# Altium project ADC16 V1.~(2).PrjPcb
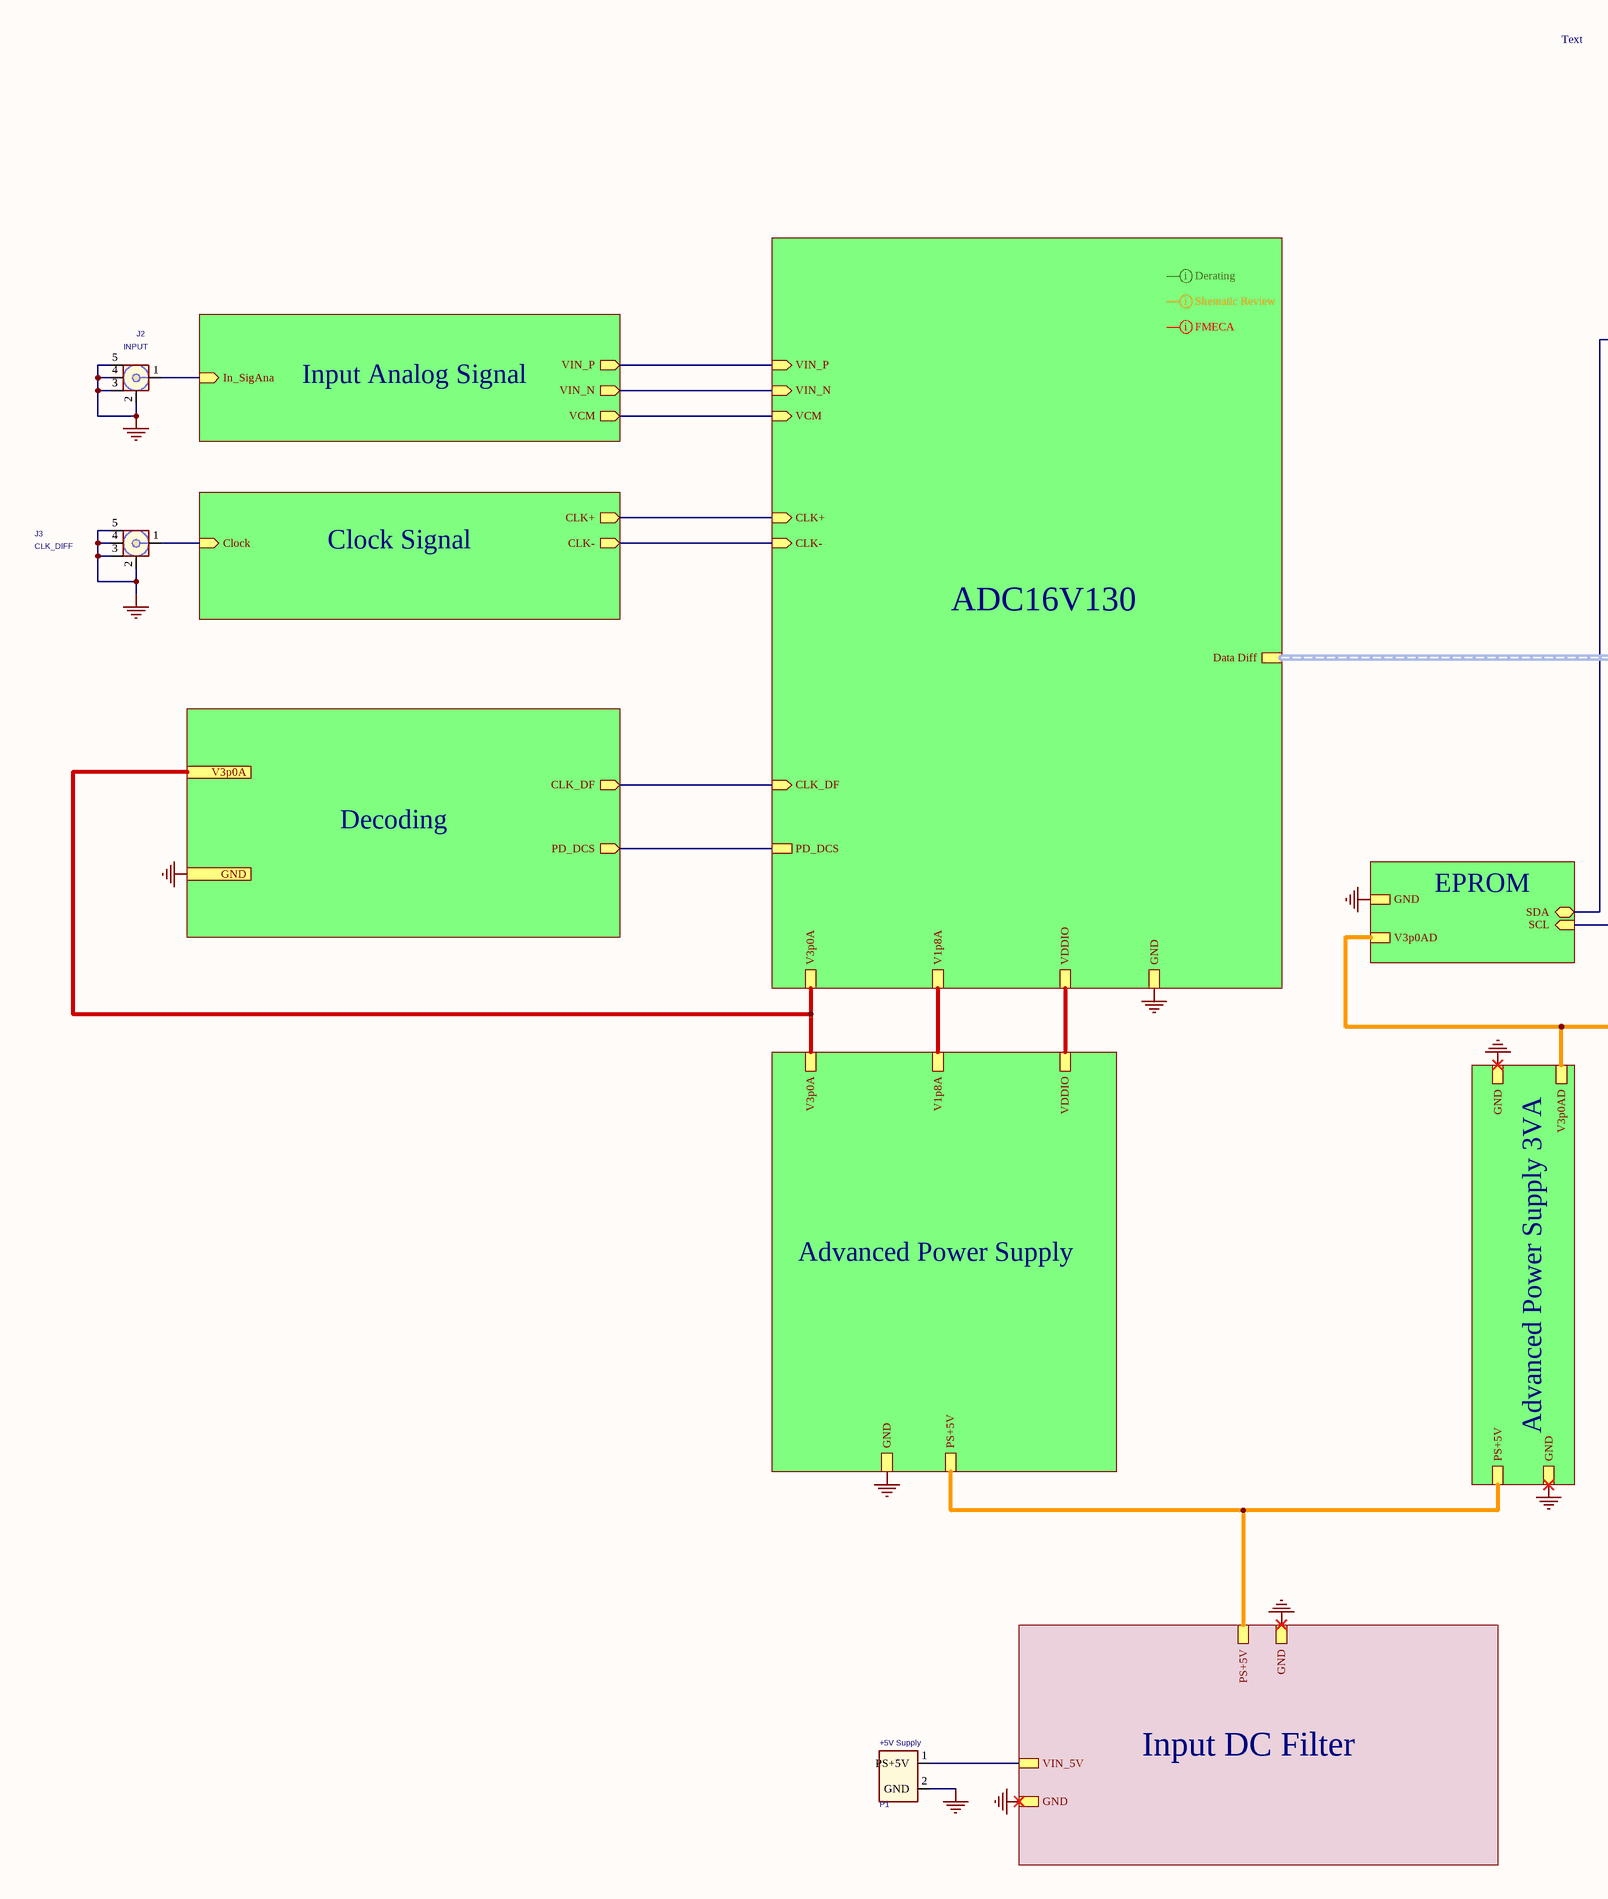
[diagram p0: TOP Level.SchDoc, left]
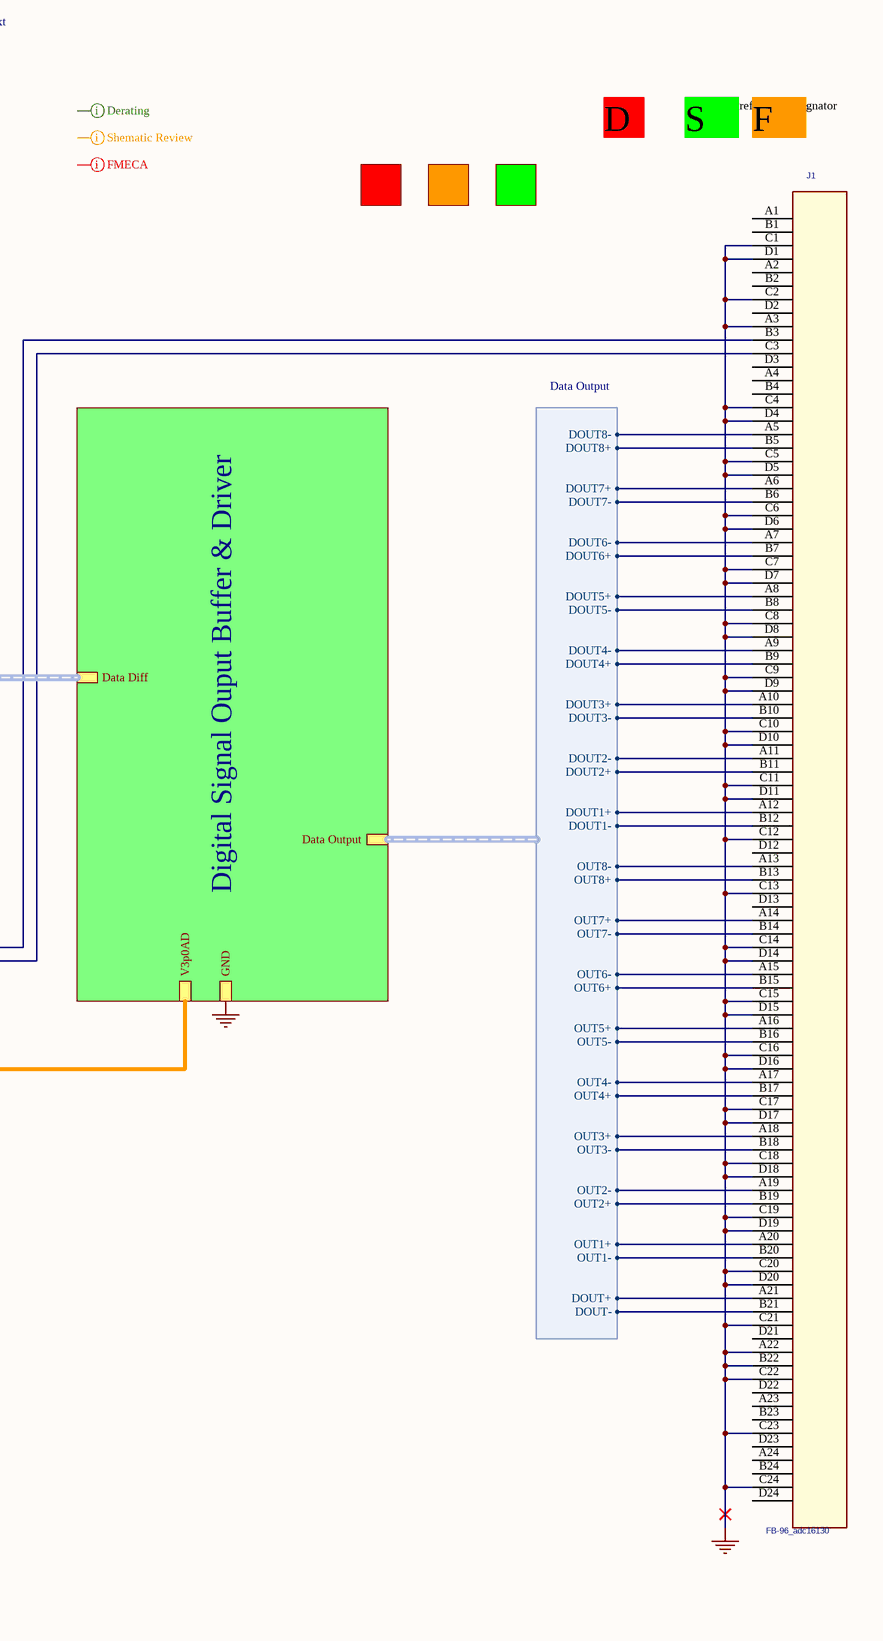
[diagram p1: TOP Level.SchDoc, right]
Revision: 1
13 sheets, 121 parts. Net scope: hierarchical (ports join the sheet entries above them; power ports are global).
Sheets:
  TOP Level.SchDoc
    ADC16V130 = [4]ADC16V130.SchDoc
    Digital Signal Ouput Buffer & Driver = [5]Digital Signal Ouput Buffer & Driver.SchDoc
    Clock Signal = [6]Clock Signal.SchDoc
    EPROM = [8]Eeprom.SchDoc
    Input Analog Signal = [9]Input Analog Signal.SchDoc
    Advanced Power Supply 3VA = [11]Advanced Power Supply 3VA.SchDoc
    Input DC Filter = [12]Input DC Filter.SchDoc
    Decoding = Decoding.SchDoc
      Decoding Code1 = [1]Decoding Code1.SchDoc
      Decoding Code2 = [10]Decoding Code2.SchDoc
    Advanced Power Supply = Advanced Power Supply.SchDoc
      Advanced Power Supply ADC1.8V = [7]Advanced Power Supply for ADC1.8V.SchDoc

## Sheet TOP Level.SchDoc: BQR Evaluation Project based on TI
size A2; Organization: BQR; Address1: Reliability Engineering; Address2: Optimized Maintenance; Address3: www.bqr.com; Address4: www.bqr-digital.com; DocumentNumber: DOC1; SheetNumber: 1; SheetTotal: 13

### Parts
J1  FB-96_adc16130  [con96-fb_16130]
J2  INPUT  [RFSMAVCLRJ8]
J3  CLK_DIFF  [RFSMAVCLRJ8]
P1  +5V Supply  [tb-2pos_plug]

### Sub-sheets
ADC16V130 = [4]ADC16V130.SchDoc: VCM (in), VIN_P (in), VIN_N (in), CLK+ (in), CLK- (in), V3p0A, PD_DCS, V1p8A, VDDIO, GND, CLK_DF (in), Data Diff (harness Data Diff)
Advanced Power Supply = Advanced Power Supply.SchDoc: PS+5V, V3p0A, GND, V1p8A, VDDIO
Advanced Power Supply 3VA = [11]Advanced Power Supply 3VA.SchDoc: V3p0AD, PS+5V, GND, GND
Clock Signal = [6]Clock Signal.SchDoc: CLK+ (out), CLK- (out), Clock (in)
Decoding = Decoding: CLK_DF (out), PD_DCS (out)
Digital Signal Ouput Buffer & Driver = [5]Digital Signal Ouput Buffer & Driver.SchDoc: V3p0AD, GND, Data Diff (harness Data Diff), Data Output (harness Data Output)
EPROM = [8]Eeprom.SchDoc: SDA (bidir), SCL (in), V3p0AD, GND
Input Analog Signal = [9]Input Analog Signal.SchDoc: VIN_P (out), VIN_N (out), VCM (out), In_SigAna (in)
Input DC Filter = [12]Input DC Filter.SchDoc: PS+5V, VIN_5V, GND, GND

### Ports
GND, V3p0A

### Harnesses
Data Output: DOUT1+, DOUT1-, DOUT2+, DOUT2-, DOUT3+, DOUT3-, DOUT4+, DOUT4-, DOUT5+, DOUT5-, DOUT6+, DOUT6-, DOUT7+, DOUT7-, DOUT8+, DOUT8-, DOUT+, DOUT-, OUT1+, OUT1-, OUT2+, OUT2-, OUT3+, OUT3-, OUT4+, OUT4-, OUT5+, OUT5-, OUT6+, OUT6-, OUT7+, OUT7-, OUT8+, OUT8-

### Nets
GND: J1.A3 J1.A22 J1.B22 J1.C1 J1.C2 J1.C4 J1.C5 J1.C6 J1.C7 J1.C8 J1.C9 J1.C10 J1.C11 J1.C12 J1.C13 J1.C14 J1.C15 J1.C16 J1.C17 J1.C18 J1.C19 J1.C20 J1.C21 J1.C22 J1.C23 J1.C24 J1.D1 J1.D4 J1.D5 J1.D6 J1.D7 J1.D8 J1.D9 J1.D10 J1.D11 J1.D14 J1.D15 J1.D16 J1.D17 J1.D18 J1.D19 J1.D20 J2.2(SHIELD2) J2.3(SHIELD3) J2.4(SHIELD4) J2.5(SHIELD5) J3.2(SHIELD2) J3.3(SHIELD3) J3.4(SHIELD4) J3.5(SHIELD5) P1.2(GND) ; port GND, sheet ADC16V130/GND, sheet Digital Signal Ouput Buffer & Driver/GND, sheet EPROM/GND, sheet Advanced Power Supply 3VA/PS+5V, sheet Advanced Power Supply 3VA/GND, sheet Advanced Power Supply 3VA/GND, sheet Input DC Filter/PS+5V, sheet Input DC Filter/GND, sheet Input DC Filter/GND, sheet Advanced Power Supply/PS+5V, sheet Advanced Power Supply/GND
V1p8A: sheet ADC16V130/V1p8A, sheet Advanced Power Supply/V1p8A
V3p0A: port V3p0A, sheet ADC16V130/V3p0A, sheet Advanced Power Supply/V3p0A
V3p0AD: sheet Digital Signal Ouput Buffer & Driver/V3p0AD, sheet EPROM/V3p0AD, sheet Advanced Power Supply 3VA/V3p0AD
VDDIO: sheet ADC16V130/VDDIO, sheet Advanced Power Supply/VDDIO
DOUT1+: J1.A12 ; sheet Digital Signal Ouput Buffer & Driver/Data Output.DOUT1+
DOUT1-: J1.B12 ; sheet Digital Signal Ouput Buffer & Driver/Data Output.DOUT1-
DOUT2+: J1.B11 ; sheet Digital Signal Ouput Buffer & Driver/Data Output.DOUT2+
DOUT2-: J1.A11 ; sheet Digital Signal Ouput Buffer & Driver/Data Output.DOUT2-
DOUT3+: J1.A10 ; sheet Digital Signal Ouput Buffer & Driver/Data Output.DOUT3+
DOUT3-: J1.B10 ; sheet Digital Signal Ouput Buffer & Driver/Data Output.DOUT3-
DOUT4+: J1.B9 ; sheet Digital Signal Ouput Buffer & Driver/Data Output.DOUT4+
DOUT4-: J1.A9 ; sheet Digital Signal Ouput Buffer & Driver/Data Output.DOUT4-
DOUT5+: J1.A8 ; sheet Digital Signal Ouput Buffer & Driver/Data Output.DOUT5+
DOUT5-: J1.B8 ; sheet Digital Signal Ouput Buffer & Driver/Data Output.DOUT5-
DOUT6+: J1.B7 ; sheet Digital Signal Ouput Buffer & Driver/Data Output.DOUT6+
DOUT6-: J1.A7 ; sheet Digital Signal Ouput Buffer & Driver/Data Output.DOUT6-
DOUT7+: J1.A6 ; sheet Digital Signal Ouput Buffer & Driver/Data Output.DOUT7+
DOUT7-: J1.B6 ; sheet Digital Signal Ouput Buffer & Driver/Data Output.DOUT7-
DOUT8+: J1.B5 ; sheet Digital Signal Ouput Buffer & Driver/Data Output.DOUT8+
DOUT8-: J1.A5 ; sheet Digital Signal Ouput Buffer & Driver/Data Output.DOUT8-
DOUT+: J1.A21 ; sheet Digital Signal Ouput Buffer & Driver/Data Output.DOUT+
DOUT-: J1.B21 ; sheet Digital Signal Ouput Buffer & Driver/Data Output.DOUT-
OUT1+: J1.A20 ; sheet Digital Signal Ouput Buffer & Driver/Data Output.OUT1+
OUT1-: J1.B20 ; sheet Digital Signal Ouput Buffer & Driver/Data Output.OUT1-
OUT2+: J1.B19 ; sheet Digital Signal Ouput Buffer & Driver/Data Output.OUT2+
OUT2-: J1.A19 ; sheet Digital Signal Ouput Buffer & Driver/Data Output.OUT2-
OUT3+: J1.A18 ; sheet Digital Signal Ouput Buffer & Driver/Data Output.OUT3+
OUT3-: J1.B18 ; sheet Digital Signal Ouput Buffer & Driver/Data Output.OUT3-
OUT4+: J1.B17 ; sheet Digital Signal Ouput Buffer & Driver/Data Output.OUT4+
OUT4-: J1.A17 ; sheet Digital Signal Ouput Buffer & Driver/Data Output.OUT4-
OUT5+: J1.A16 ; sheet Digital Signal Ouput Buffer & Driver/Data Output.OUT5+
OUT5-: J1.B16 ; sheet Digital Signal Ouput Buffer & Driver/Data Output.OUT5-
OUT6+: J1.B15 ; sheet Digital Signal Ouput Buffer & Driver/Data Output.OUT6+
OUT6-: J1.A15 ; sheet Digital Signal Ouput Buffer & Driver/Data Output.OUT6-
OUT7+: J1.A14 ; sheet Digital Signal Ouput Buffer & Driver/Data Output.OUT7+
OUT7-: J1.B14 ; sheet Digital Signal Ouput Buffer & Driver/Data Output.OUT7-
OUT8+: J1.B13 ; sheet Digital Signal Ouput Buffer & Driver/Data Output.OUT8+
OUT8-: J1.A13 ; sheet Digital Signal Ouput Buffer & Driver/Data Output.OUT8-
VIN_5V: P1.1(PS+5V) ; sheet Input DC Filter/VIN_5V
NetC1_1: sheet ADC16V130/VCM, sheet Input Analog Signal/VCM
NetC17_1: J2.1(CENTER) ; sheet Input Analog Signal/In_SigAna
NetC21_1: sheet ADC16V130/VIN_P, sheet Input Analog Signal/VIN_P
NetC21_2: sheet ADC16V130/VIN_N, sheet Input Analog Signal/VIN_N
NetC32_1: J3.1(CENTER) ; sheet Clock Signal/Clock
NetC35_1: sheet ADC16V130/CLK+, sheet Clock Signal/CLK+
NetC35_2: sheet ADC16V130/CLK-, sheet Clock Signal/CLK-
NetJ1_B3: J1.B3 ; sheet EPROM/SDA
NetJ1_C3: J1.C3 ; sheet EPROM/SCL
NetJP1_2: sheet ADC16V130/CLK_DF, sheet Decoding/CLK_DF
NetJP2_2: sheet ADC16V130/PD_DCS, sheet Decoding/PD_DCS

Not connected (* = marked no-connect by the designer): J1 A1(1) A2(5) A4(13) A23(89) A24(93) B1(2) B2(6) B4(14) B23(90) B24(94) D2(8) D3(12) D12(48) D13(52) D21(84) D22(88) D23(92) D24(96)

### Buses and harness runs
harness sheet ADC16V130/Data Diff = sheet Digital Signal Ouput Buffer & Driver/Data Diff

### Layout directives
BQR1: Stam1: (no net found under the mark)
mark named Shematic Review: (no net found under the mark)
mark named FMECA: (no net found under the mark)
mark named Derating: (no net found under the mark)

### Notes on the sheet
- Text
- D
- Type @ to refer to a designator
- S
- F

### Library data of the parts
J1 = CON-FB96-ADC16130: 2MM FB,IS,ASY,024,SIG,HDR,SL; Manufacturer: AMP/Tyco; Manufacturer P/N: 223514-1; fiX_Manuf: JOHNSON; Catalog Number: CON00005; fiX_Func: Buffer & Driver (9)
J2 = SMA_CONN_4: SMA Connector Jack, Female Socket 50 Ohm Board Edge, End Launch Solder Tab; Manufacturer: JOHNSON; Manufacturer P/N: 142-0701-851; fiX_Manuf: Samtec; Catalog Number: CON00004; fiX_Func: Input circuit (4)
J3 = SMA_CONN_5: SMA Connector Jack, Female Socket 50 Ohm Board Edge, End Launch Solder Tab; Manufacturer P/N: 142-0701-851; Manufacturer: JOHNSON; fiX_Manuf: Samtec; Catalog Number: CON00004; fiX_Func: Clock signal (6)
P1 = TB2_1: CONN RCPT SUR 2POS .8MM TIN; Manufacturer P/N: 02SUR-32S; Manufacturer: JST; fiX_Manuf: Vishay; Catalog Number: CON00003; fiX_Func: DC Filter (12); SDTA_V(Vdiel): 5

## Sheet [4]ADC16V130.SchDoc: ADC16V130
size A3; Organization: BQR; Address1: Reliability Engineering; Address2: Optimized Maintenance; Address3: www.bqr.com; Address4: www.bqr-digital.com; DocumentNumber: DOC5; SheetNumber: 2; SheetTotal: 13
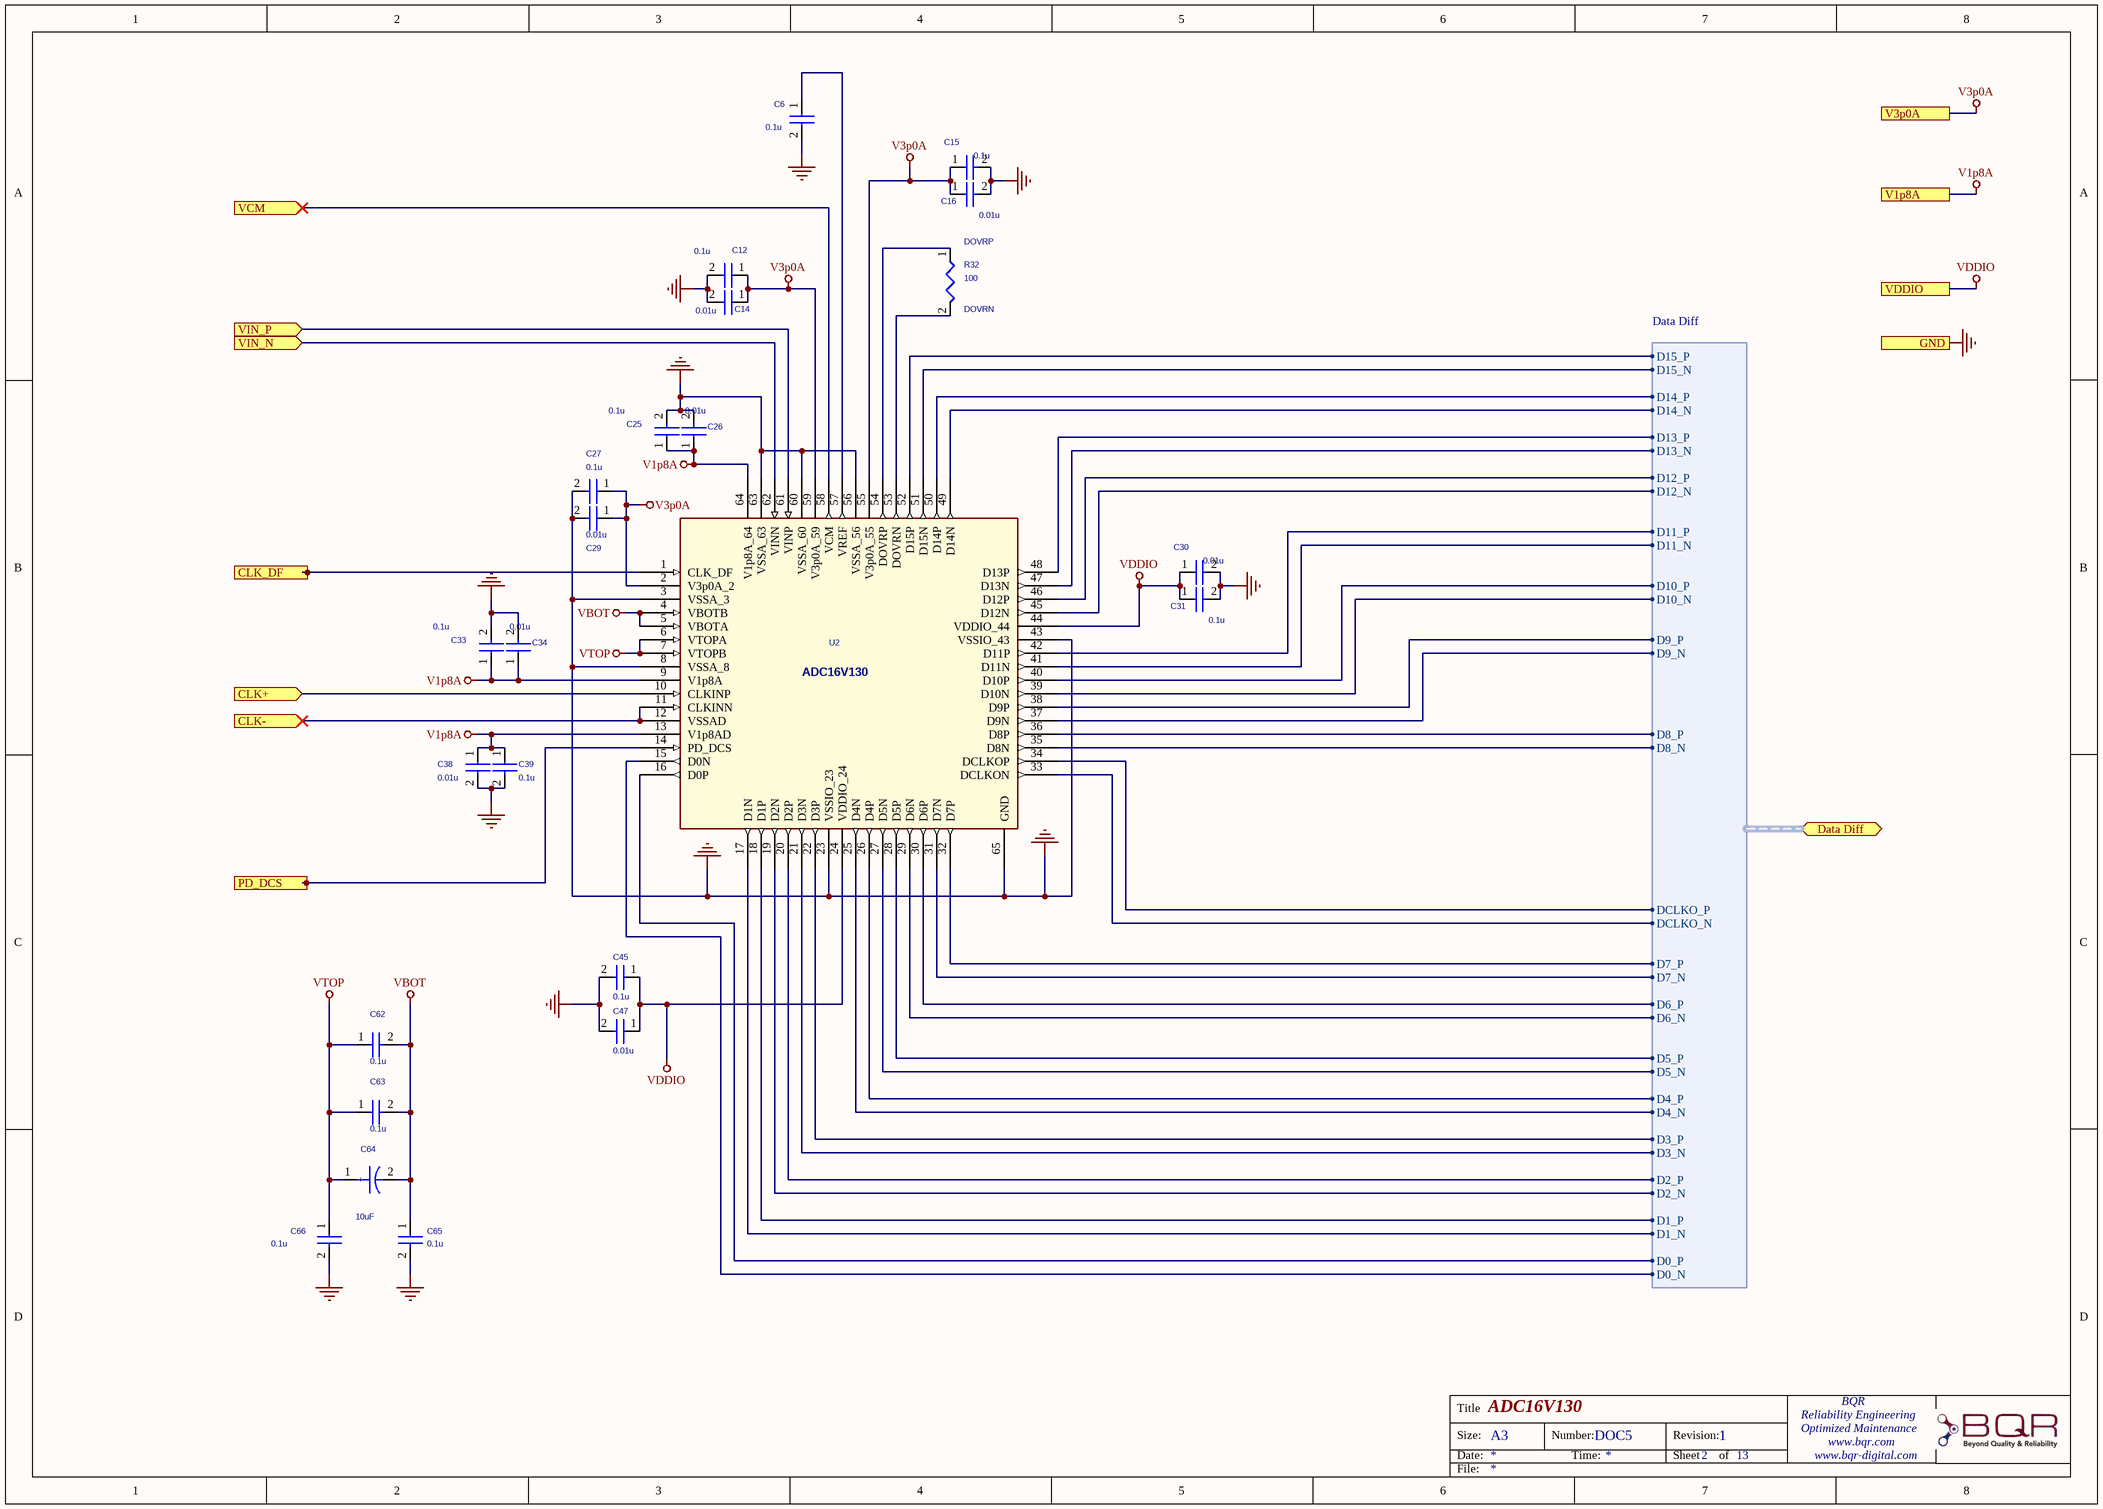
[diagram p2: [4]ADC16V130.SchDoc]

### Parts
C6  0.1u  [0402]
C12  0.1u  [0201]
C14  0.01u  [0402]
C15  0.1u  [0201]
C16  0.01u  [0402]
C25  0.1u  [0201]
C26  0.01u  [0402]
C27  0.1u  [0402]
C29  0.01u  [0402]
C30  0.01u  [0402]
C31  0.1u  [0402]
C33  0.1u  [0402]
C34  0.01u  [0402]
C38  0.01u  [0402]
C39  0.1u  [0402]
C45  0.1u  [0402]
C47  0.01u  [0402]
C62  0.1u  [0402]
C63  0.1u  [0402]
C64  10uF  [cap_a-case]
C65  0.1u  [0402]
C66  0.1u  [0402]
R32  100  [0402]
U2  ADC16V130  [llp64_16130_no-skt]

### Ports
CLK+ (in), CLK- (in), CLK_DF (in), Data Diff (bidir, harness Data Diff), GND, PD_DCS, V1p8A, V3p0A, VCM (in), VDDIO, VIN_N (in), VIN_P (in)

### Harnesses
Data Diff: D0_N, D0_P, D1_N, D1_P, D2_N, D2_P, D3_N, D3_P, D4_N, D4_P, D5_N, D5_P, D6_N, D6_P, D7_N, D7_P, D8_N, D8_P, D9_N, D9_P, D10_N, D10_P, D11_N, D11_P, D12_N, D12_P, D13_N, D13_P, D14_N, D14_P, D15_N, D15_P, DCLKO_N, DCLKO_P

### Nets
GND: C6.2 C12.2 C14.2 C15.2 C16.2 C25.2 C26.2 C27.2 C29.2 C30.2 C31.2 C33.2 C34.2 C38.2 C39.2 C45.2 C47.2 C65.2 C66.2 U2.3(VSSA_3) U2.8(VSSA_8) U2.23(VSSIO_23) U2.43(VSSIO_43) U2.56(VSSA_56) U2.60(VSSA_60) U2.63(VSSA_63) U2.65(GND) ; port GND
V1p8A: C25.1 C26.1 C33.1 C34.1 C38.1 C39.1 U2.9(V1p8A) U2.13(V1p8AD) U2.64(V1p8A_64) ; port V1p8A
V3p0A: C12.1 C14.1 C15.1 C16.1 C27.1 C29.1 U2.2(V3p0A_2) U2.55(V3p0A_55) U2.59(V3p0A_59) ; port V3p0A
VBOT: C62.2 C63.2 C64.2 C65.1 U2.4(VBOTB) U2.5(VBOTA)
VDDIO: C30.1 C31.1 C45.1 C47.1 U2.24(VDDIO_24) U2.44(VDDIO_44) ; port VDDIO
VTOP: C62.1 C63.1 C64.1 C66.1 U2.6(VTOPA) U2.7(VTOPB)
D0_N: U2.15(D0N) ; port Data Diff.D0_N
D0_P: U2.16(D0P) ; port Data Diff.D0_P
D1_N: U2.17(D1N) ; port Data Diff.D1_N
D1_P: U2.18(D1P) ; port Data Diff.D1_P
D2_N: U2.19(D2N) ; port Data Diff.D2_N
D2_P: U2.20(D2P) ; port Data Diff.D2_P
D3_N: U2.21(D3N) ; port Data Diff.D3_N
D3_P: U2.22(D3P) ; port Data Diff.D3_P
D4_N: U2.25(D4N) ; port Data Diff.D4_N
D4_P: U2.26(D4P) ; port Data Diff.D4_P
D5_N: U2.27(D5N) ; port Data Diff.D5_N
D5_P: U2.28(D5P) ; port Data Diff.D5_P
D6_N: U2.29(D6N) ; port Data Diff.D6_N
D6_P: U2.30(D6P) ; port Data Diff.D6_P
D7_N: U2.31(D7N) ; port Data Diff.D7_N
D7_P: U2.32(D7P) ; port Data Diff.D7_P
D8_N: U2.35(D8N) ; port Data Diff.D8_N
D8_P: U2.36(D8P) ; port Data Diff.D8_P
D9_N: U2.37(D9N) ; port Data Diff.D9_N
D9_P: U2.38(D9P) ; port Data Diff.D9_P
D10_N: U2.39(D10N) ; port Data Diff.D10_N
D10_P: U2.40(D10P) ; port Data Diff.D10_P
D11_N: U2.41(D11N) ; port Data Diff.D11_N
D11_P: U2.42(D11P) ; port Data Diff.D11_P
D12_N: U2.45(D12N) ; port Data Diff.D12_N
D12_P: U2.46(D12P) ; port Data Diff.D12_P
D13_N: U2.47(D13N) ; port Data Diff.D13_N
D13_P: U2.48(D13P) ; port Data Diff.D13_P
D14_N: U2.49(D14N) ; port Data Diff.D14_N
D14_P: U2.50(D14P) ; port Data Diff.D14_P
D15_N: U2.51(D15N) ; port Data Diff.D15_N
D15_P: U2.52(D15P) ; port Data Diff.D15_P
DCLKO_N: U2.33(DCLKON) ; port Data Diff.DCLKO_N
DCLKO_P: U2.34(DCLKOP) ; port Data Diff.DCLKO_P
NetC1_1: U2.58(VCM) ; port VCM
NetC6_1: C6.1 U2.57(VREF)
NetC21_1: U2.61(VINP) ; port VIN_P
NetC21_2: U2.62(VINN) ; port VIN_N
NetC35_1: U2.10(CLKINP) ; port CLK+
NetC35_2: U2.11(CLKINN) U2.12(VSSAD) ; port CLK-
NetJP1_2: U2.1(CLK_DF) ; port CLK_DF
NetJP2_2: U2.14(PD_DCS) ; port PD_DCS
NetR32_1: R32.1 U2.54(DOVRP)
NetR32_2: R32.2 U2.53(DOVRN)

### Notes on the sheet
- (near R32) DOVRP
- (near R32) DOVRN

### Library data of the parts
C6 = Capacitor_4: CAP CER 0.1UF 10V X5R 0402; Manufacturer P/N: GRM155R61A104KA01D; Manufacturer: Murata; Catalog Number: CAP00026; fiX_Func: ADC (10)
C12 C15 = Cap_1: CAP CER 0.1UF 6.3V X5R 0201; Manufacturer P/N: GRM033R60J104KE19D; Manufacturer: Murata; Catalog Number: CAP00002; SDTA_V(Voltage): 3; fiX_Func: ADC (10); SDTA_V(): 5
C14 C16 C29 = Cap_1: CAP CER 10000PF 50V X7R 0402; Manufacturer P/N: GRM155R71H103KA88D; Manufacturer: Murata; Catalog Number: CAP00027; SDTA_V(Voltage): 3; fiX_Func: ADC (10); SDTA_V(): 5
C25 = Cap_1: CAP CER 0.1UF 6.3V X5R 0201; Manufacturer P/N: GRM033R60J104KE19D; Manufacturer: Murata; Catalog Number: CAP00002; SDTA_V(Voltage): 1.8; fiX_Func: ADC (10)
C26 C34 = Cap_1: CAP CER 10000PF 50V X7R 0402; Manufacturer P/N: GRM155R71H103KA88D; Manufacturer: Murata; Catalog Number: CAP00027; SDTA_V(Voltage): 1.8; fiX_Func: ADC (10)
C27 = Cap_1: CAP CER 0.1UF 10V X5R 0402; Manufacturer P/N: GRM155R61A104KA01D; Manufacturer: Murata; Catalog Number: CAP00026; SDTA_V(Voltage): 3; fiX_Func: ADC (10); SDTA_V(): 5
C30 = Cap_1: CAP CER 10000PF 50V X7R 0402; Manufacturer P/N: GRM155R71H103KA88D; Manufacturer: Murata; Catalog Number: CAP00027; SDTA_V(Voltage): 25; fiX_Func: Buffer & Driver (9)
C31 = Cap_1: CAP CER 0.1UF 10V X5R 0402; Manufacturer P/N: GRM155R61A104KA01D; Manufacturer: Murata; Catalog Number: CAP00026; SDTA_V(Voltage): 25; fiX_Func: Buffer & Driver (9)
C33 C39 = Cap_1: CAP CER 0.1UF 10V X5R 0402; Manufacturer P/N: GRM155R61A104KA01D; Manufacturer: Murata; Catalog Number: CAP00026; SDTA_V(Voltage): 1.8; fiX_Func: ADC (10)
C38 = Cap_1: CAP CER 10000PF 50V X7R 0402; Manufacturer P/N: GRM155R71H103KA88D; Manufacturer: Murata; Catalog Number: CAP00027; SDTA_V(Voltage): 1.8; fiX_Func: Advanced Power Supply 1.8V (3)
C45 = Cap_1: CAP CER 0.1UF 10V X5R 0402; Manufacturer P/N: GRM155R61A104KA01D; Manufacturer: Murata; Catalog Number: CAP00026; SDTA_V(Voltage): 25; fiX_Func: ADC (10)
C47 = Cap_1: CAP CER 10000PF 50V X7R 0402; Manufacturer P/N: GRM155R71H103KA88D; Manufacturer: Murata; Catalog Number: CAP00027; SDTA_V(Voltage): 25; fiX_Func: ADC (10)
C62 C63 = Capacitor_3: CAP CER 0.1UF 10V X5R 0402; Manufacturer P/N: GRM155R61A104KA01D; Manufacturer: Murata; Catalog Number: CAP00026; fiX_Func: ADC (10)
C64 = Cap_Polar_1: CAP TANT 10UF 10V 20% 1206; Manufacturer P/N: F931A106MAA; Manufacturer: Nichicon; fiX_Manuf: Murata; Catalog Number: CAP00023; fiX_Func: ADC (10)
C65 = Capacitor_4: CAP CER 0.1UF 10V X5R 0402; Manufacturer P/N: GRM155R61A104KA01D; Manufacturer: Murata; Catalog Number: CAP00026; fiX_Func: ADC (10); SDTA_V(Voltage): 35
C66 = Capacitor_4: CAP CER 0.1UF 10V X5R 0402; Manufacturer P/N: GRM155R61A104KA01D; Manufacturer: Murata; Catalog Number: CAP00026; fiX_Func: ADC (10); SDTA_V(Voltage): 21
R32 = Resistor_3: RES SMD 100 OHM 1% 1/16W 0402; Manufacturer: Vishay; Manufacturer P/N: CRCW0402100RFKED; Catalog Number: RES00014; fiX_Func: ADC (10)
U2 = ADC16130_LLP_13: IC ADC 16BIT 130MSPS LVDS 64WQFN; Manufacturer P/N: ADC16V130CISQE/NOPB; Manufacturer: Texas Instruments; fiX_Manuf: Atmel; Catalog Number: IC00007; SDTA_I(Iout): 0.01; SDTA_P(Power): 0.2; SDTA_Par6(Freq[Mhz]): 10; SDTA_V(Vsupply): 5; fiX_Func: ADC (10)

## Sheet [5]Digital Signal Ouput Buffer & Driver.SchDoc: Digital Signal Ouput Buffer & Driver
size A2; Organization: BQR; Address1: Reliability Engineering; Address2: Optimized Maintenance; Address3: www.bqr.com; Address4: www.bqr-digital.com; DocumentNumber: DOC6; SheetNumber: 3; SheetTotal: 13
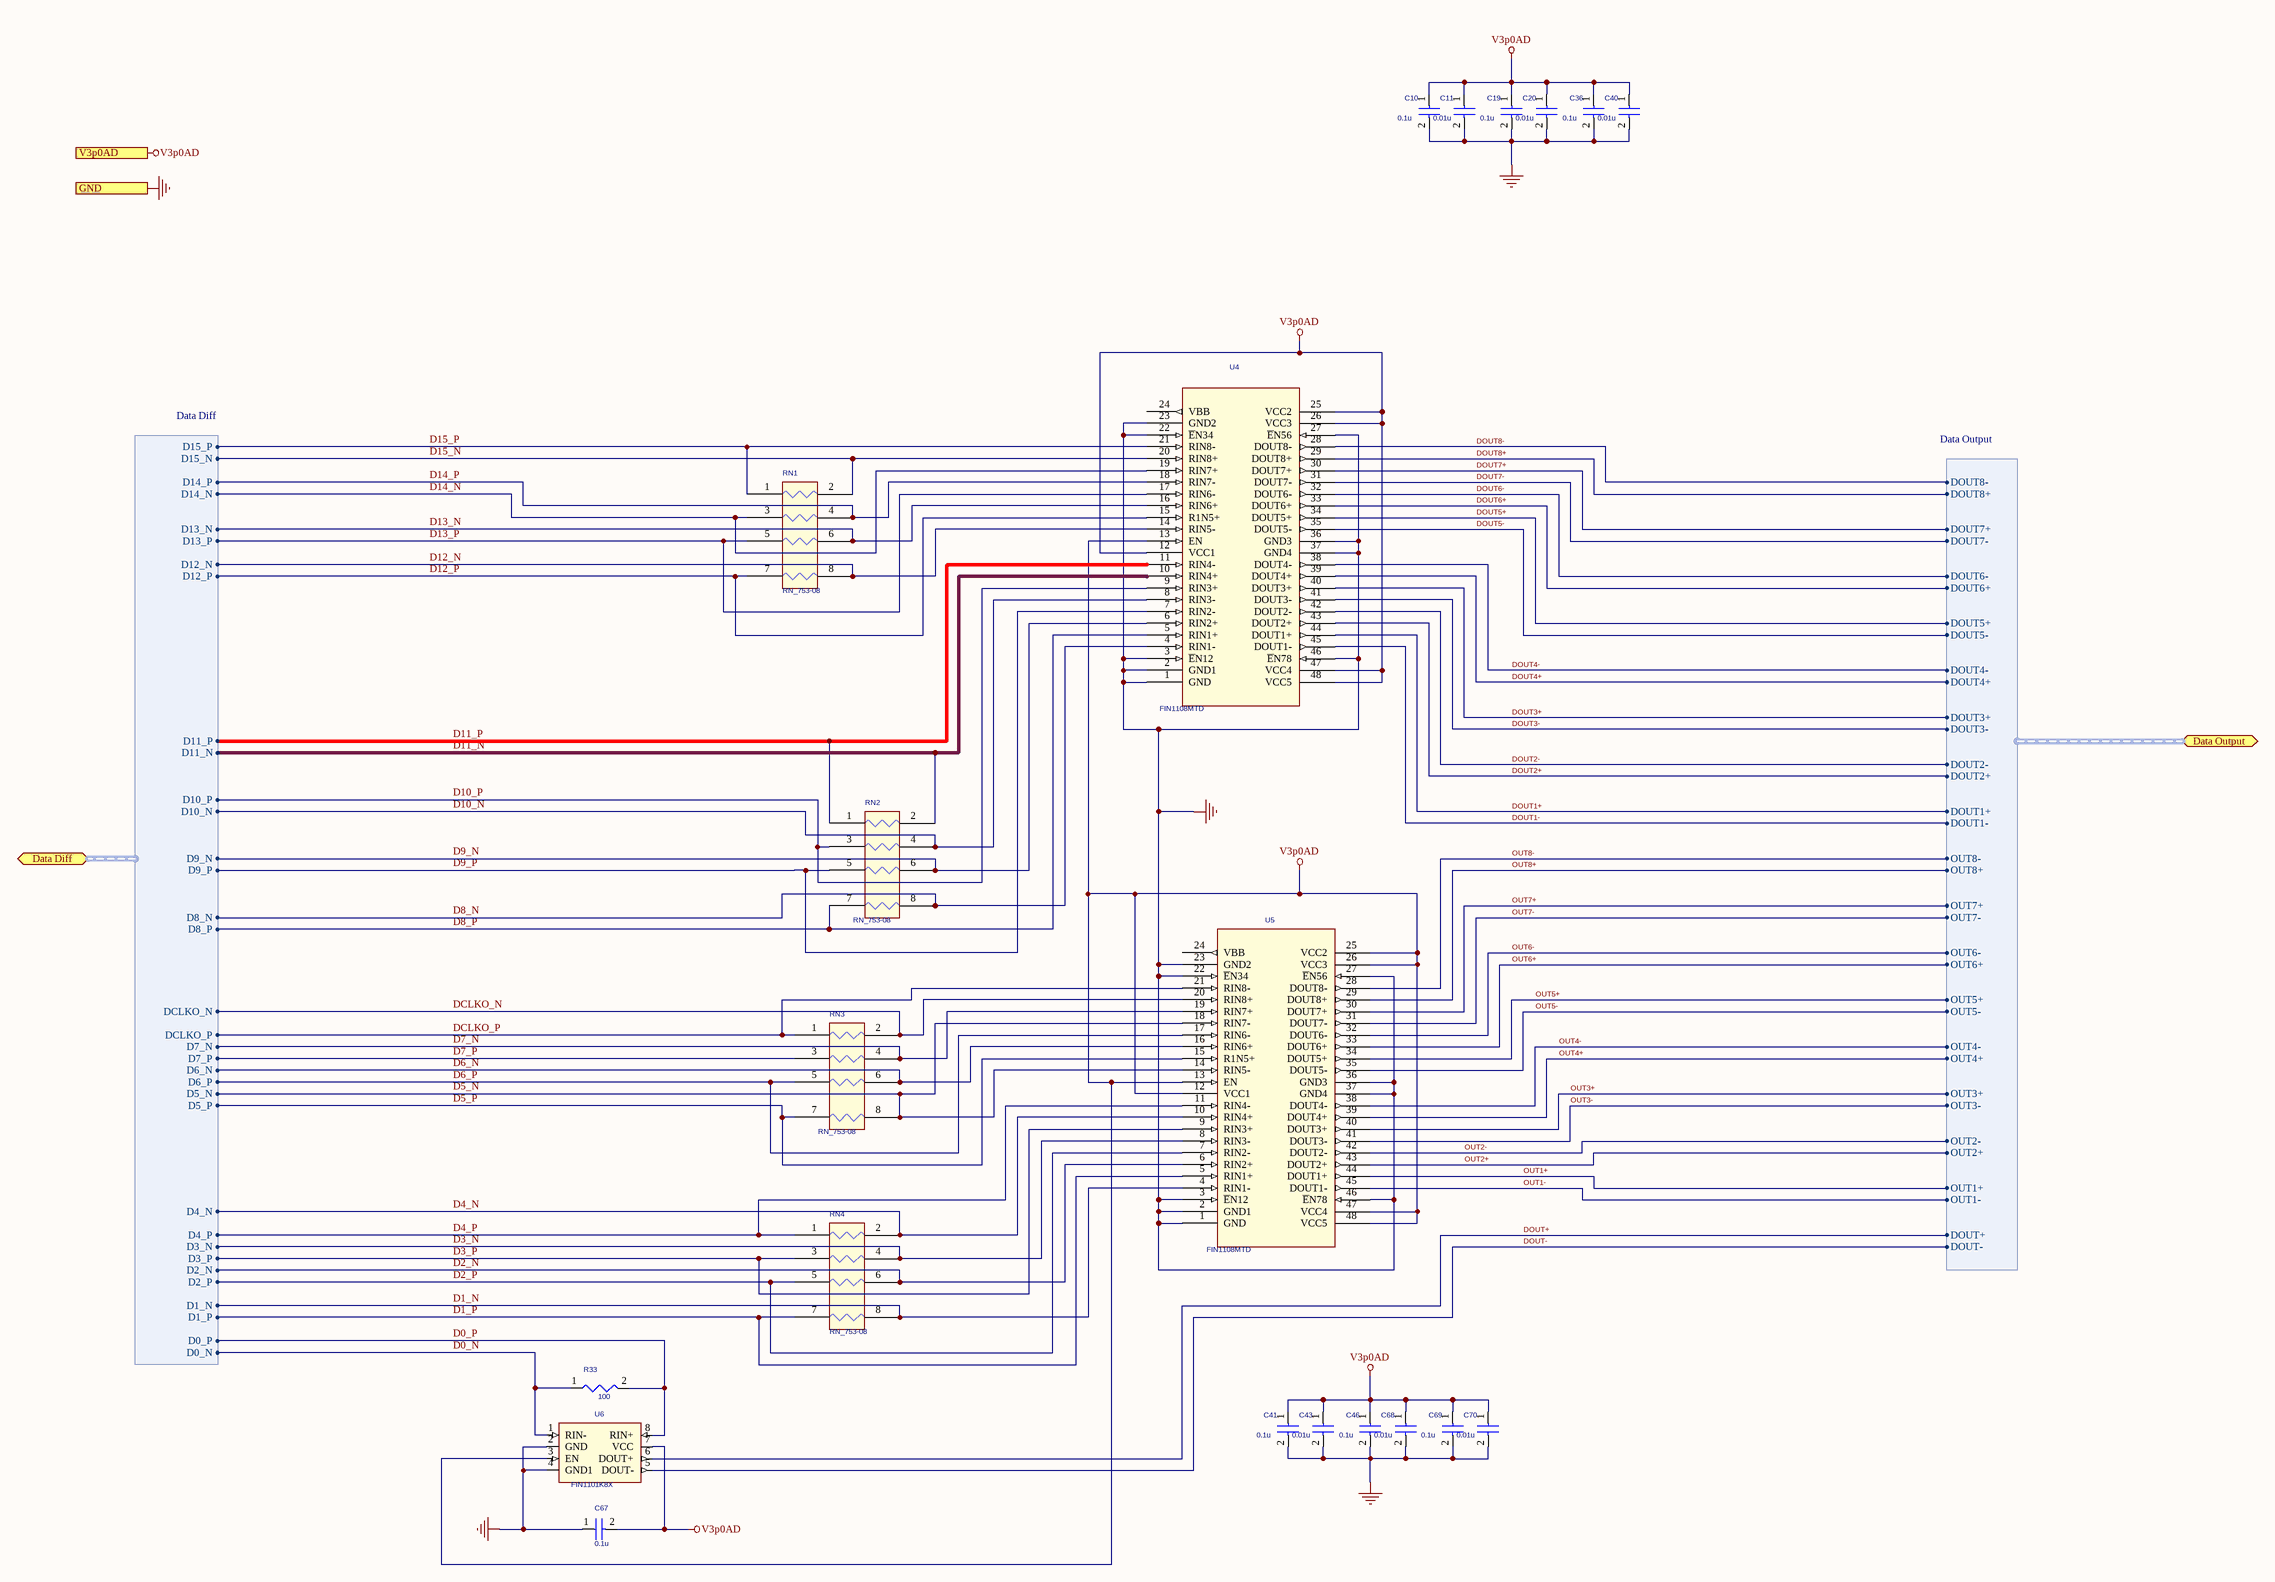
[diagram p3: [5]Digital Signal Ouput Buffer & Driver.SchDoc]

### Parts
C10  0.1u  [0402]
C11  0.01u  [0402]
C19  0.1u  [0402]
C20  0.01u  [0402]
C36  0.1u  [0402]
C40  0.01u  [0402]
C41  0.1u  [0402]
C43  0.01u  [0402]
C46  0.1u  [0402]
C67  0.1u  [0402]
C68  0.01u  [0402]
C69  0.1u  [0402]
C70  0.01u  [0402]
R33  100  [0402]
RN1  RN_753-08  [753083101gtr]
RN2  RN_753-08  [753083101gtr]
RN3  RN_753-08  [753083101gtr]
RN4  RN_753-08  [753083101gtr]
U4  FIN1108MTD  [tssop48_fin1108mtd]
U5  FIN1108MTD  [tssop48_fin1108mtd]
U6  FIN1101K8X  [us8_fin1101k8x]

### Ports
Data Diff (bidir, harness Data Diff), Data Output (bidir, harness Data Output), GND, V3p0AD

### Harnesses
Data Diff: D0_N, D0_P, D1_N, D1_P, D2_N, D2_P, D3_N, D3_P, D4_N, D4_P, D5_N, D5_P, D6_N, D6_P, D7_N, D7_P, D8_N, D8_P, D9_N, D9_P, D10_N, D10_P, D11_N, D11_P, D12_N, D12_P, D13_N, D13_P, D14_N, D14_P, D15_N, D15_P, DCLKO_N, DCLKO_P
Data Output: DOUT1+, DOUT1-, DOUT2+, DOUT2-, DOUT3+, DOUT3-, DOUT4+, DOUT4-, DOUT5+, DOUT5-, DOUT6+, DOUT6-, DOUT7+, DOUT7-, DOUT8+, DOUT8-, DOUT+, DOUT-, OUT1+, OUT1-, OUT2+, OUT2-, OUT3+, OUT3-, OUT4+, OUT4-, OUT5+, OUT5-, OUT6+, OUT6-, OUT7+, OUT7-, OUT8+, OUT8-

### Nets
GND: C10.2 C11.2 C19.2 C20.2 C36.2 C40.2 C41.2 C43.2 C46.2 C67.1 C68.2 C69.2 C70.2 U4.1(GND) U4.2(GND1) U4.3(~{E}N12) U4.22(~{E}N34) U4.23(GND2) U4.27(~{E}N56) U4.36(GND3) U4.37(GND4) U4.46(~{E}N78) U5.1(GND) U5.2(GND1) U5.3(~{E}N12) U5.22(~{E}N34) U5.23(GND2) U5.27(~{E}N56) U5.36(GND3) U5.37(GND4) U5.46(~{E}N78) U6.2(GND) U6.4(GND1) ; port GND
V3p0AD: C10.1 C11.1 C19.1 C20.1 C36.1 C40.1 C41.1 C43.1 C46.1 C67.2 C68.1 C69.1 C70.1 U4.12(VCC1) U4.13(EN) U4.25(VCC2) U4.26(VCC3) U4.47(VCC4) U4.48(VCC5) U5.12(VCC1) U5.13(EN) U5.25(VCC2) U5.26(VCC3) U5.47(VCC4) U5.48(VCC5) U6.3(EN) U6.7(VCC) ; port V3p0AD
D0_N: R33.1 U6.1(RIN-) ; port Data Diff.D0_N
D0_P: R33.2 U6.8(RIN+) ; port Data Diff.D0_P
D1_N: RN4.8 U5.4(RIN1-) ; port Data Diff.D1_N
D1_P: RN4.7 U5.5(RIN1+) ; port Data Diff.D1_P
D2_N: RN4.6 U5.6(RIN2+) ; port Data Diff.D2_N
D2_P: RN4.5 U5.7(RIN2-) ; port Data Diff.D2_P
D3_N: RN4.4 U5.8(RIN3-) ; port Data Diff.D3_N
D3_P: RN4.3 U5.9(RIN3+) ; port Data Diff.D3_P
D4_N: RN4.2 U5.10(RIN4+) ; port Data Diff.D4_N
D4_P: RN4.1 U5.11(RIN4-) ; port Data Diff.D4_P
D5_N: RN3.8 U5.14(RIN5-) U5.18(RIN7-) ; port Data Diff.D5_N
D5_P: RN3.7 U5.15(R1N5+) ; port Data Diff.D5_P
D6_N: RN3.6 U5.16(RIN6+) ; port Data Diff.D6_N
D6_P: RN3.5 U5.17(RIN6-) ; port Data Diff.D6_P
D7_N: RN3.4 U5.19(RIN7+) ; port Data Diff.D7_N
D7_P: RN3.3 ; port Data Diff.D7_P
D8_N: RN2.8 U4.4(RIN1-) ; port Data Diff.D8_N
D8_P: RN2.7 U4.5(RIN1+) ; port Data Diff.D8_P
D9_N: RN2.6 U4.6(RIN2+) ; port Data Diff.D9_N
D9_P: RN2.5 U4.7(RIN2-) ; port Data Diff.D9_P
D10_N: RN2.4 U4.8(RIN3-) ; port Data Diff.D10_N
D10_P: RN2.3 U4.9(RIN3+) ; port Data Diff.D10_P
D11_N: RN2.2 U4.10(RIN4+) ; port Data Diff.D11_N
D11_P: RN2.1 U4.11(RIN4-) ; port Data Diff.D11_P
D12_N: RN1.8 U4.14(RIN5-) ; port Data Diff.D12_N
D12_P: RN1.7 U4.15(R1N5+) ; port Data Diff.D12_P
D13_N: RN1.6 U4.16(RIN6+) ; port Data Diff.D13_N
D13_P: RN1.5 U4.17(RIN6-) ; port Data Diff.D13_P
D14_N: RN1.3 U4.19(RIN7+) ; port Data Diff.D14_N
D14_P: RN1.4 U4.18(RIN7-) ; port Data Diff.D14_P
D15_N: RN1.2 U4.20(RIN8+) ; port Data Diff.D15_N
D15_P: RN1.1 U4.21(RIN8-) ; port Data Diff.D15_P
DCLKO_N: RN3.2 U5.20(RIN8+) ; port Data Diff.DCLKO_N
DCLKO_P: RN3.1 U5.21(RIN8-) ; port Data Diff.DCLKO_P
DOUT1+: U4.44(DOUT1+) ; port Data Output.DOUT1+
DOUT1-: U4.45(DOUT1-) ; port Data Output.DOUT1-
DOUT2+: U4.43(DOUT2+) ; port Data Output.DOUT2+
DOUT2-: U4.42(DOUT2-) ; port Data Output.DOUT2-
DOUT3+: U4.40(DOUT3+) ; port Data Output.DOUT3+
DOUT3-: U4.41(DOUT3-) ; port Data Output.DOUT3-
DOUT4+: U4.39(DOUT4+) ; port Data Output.DOUT4+
DOUT4-: U4.38(DOUT4-) ; port Data Output.DOUT4-
DOUT5+: U4.34(DOUT5+) ; port Data Output.DOUT5+
DOUT5-: U4.35(DOUT5-) ; port Data Output.DOUT5-
DOUT6+: U4.33(DOUT6+) ; port Data Output.DOUT6+
DOUT6-: U4.32(DOUT6-) ; port Data Output.DOUT6-
DOUT7+: U4.30(DOUT7+) ; port Data Output.DOUT7+
DOUT7-: U4.31(DOUT7-) ; port Data Output.DOUT7-
DOUT8+: U4.29(DOUT8+) ; port Data Output.DOUT8+
DOUT8-: U4.28(DOUT8-) ; port Data Output.DOUT8-
DOUT+: U6.6(DOUT+) ; port Data Output.DOUT+
DOUT-: U6.5(DOUT-) ; port Data Output.DOUT-
OUT1+: U5.44(DOUT1+) ; port Data Output.OUT1+
OUT1-: U5.45(DOUT1-) ; port Data Output.OUT1-
OUT2+: U5.43(DOUT2+) ; port Data Output.OUT2+
OUT2-: U5.42(DOUT2-) ; port Data Output.OUT2-
OUT3+: U5.40(DOUT3+) ; port Data Output.OUT3+
OUT3-: U5.41(DOUT3-) ; port Data Output.OUT3-
OUT4+: U5.39(DOUT4+) ; port Data Output.OUT4+
OUT4-: U5.38(DOUT4-) ; port Data Output.OUT4-
OUT5+: U5.34(DOUT5+) ; port Data Output.OUT5+
OUT5-: U5.35(DOUT5-) ; port Data Output.OUT5-
OUT6+: U5.33(DOUT6+) ; port Data Output.OUT6+
OUT6-: U5.32(DOUT6-) ; port Data Output.OUT6-
OUT7+: U5.30(DOUT7+) ; port Data Output.OUT7+
OUT7-: U5.31(DOUT7-) ; port Data Output.OUT7-
OUT8+: U5.29(DOUT8+) ; port Data Output.OUT8+
OUT8-: U5.28(DOUT8-) ; port Data Output.OUT8-

Not connected (* = marked no-connect by the designer): U4 24(VBB); U5 24(VBB)

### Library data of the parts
C10 C19 C36 C41 C46 C69 = Capacitor_4: CAP CER 0.1UF 10V X5R 0402; Manufacturer P/N: GRM155R61A104KA01D; Manufacturer: Murata; Catalog Number: CAP00026; SDTA_V(Voltage): 3; fiX_Func: Advanced Power Supply 3V (2)
C11 C20 C40 C43 C68 C70 = Capacitor_4: CAP CER 10000PF 50V X7R 0402; Manufacturer P/N: GRM155R71H103KA88D; Manufacturer: Murata; Catalog Number: CAP00027; SDTA_V(Voltage): 3; fiX_Func: Advanced Power Supply 3V (2)
C67 = Cap_1: CAP CER 0.1UF 10V X5R 0402; Manufacturer P/N: GRM155R61A104KA01D; Manufacturer: Murata; Catalog Number: CAP00026; SDTA_V(Voltage): 3; fiX_Func: ADC (10)
R33 = Resistor_3: RES SMD 100 OHM 1% 1/16W 0402; Manufacturer P/N: CRCW0402100RFKED; Manufacturer: Vishay; Catalog Number: RES00014; fiX_Func: ADC (10)
RN1-RN4 = RN_753-08: RES ARRAY 4 RES 100 OHM 8SRT; Manufacturer: CTS; Catalog Number: RES00006; fiX_Func: Buffer & Driver (9)
U4 U5 = FIN1108MTD_1: IC REDRIVER LVDS 8CH 48TSSOP; Manufacturer: Fairchild; Catalog Number: IC00025; fiX_Func: Buffer & Driver (9)
U6 = FIN1101K8X_0: IC REDRIVER LVDS 1CH 1.6GBPS US8; Manufacturer: Fairchild; fiX_Manuf: Texas Instruments; Catalog Number: IC00024; fiX_Func: ADC (10)

## Sheet [6]Clock Signal.SchDoc: Clock Signal
size A4; Organization: BQR; Address1: Reliability Engineering; Address2: Optimized Maintenance; Address3: www.bqr.com; Address4: www.bqr-digital.com; DocumentNumber: DOC7; SheetNumber: 4; SheetTotal: 13
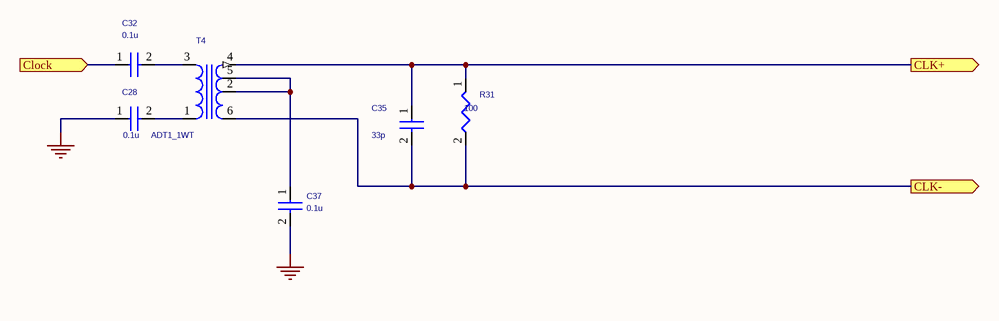
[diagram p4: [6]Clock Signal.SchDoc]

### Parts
C28  0.1u  [0603]
C32  0.1u  [0603]
C35  33p  [0402]
C37  0.1u  [0603]
R31  100  [0402]
T4  ADT1_1WT  [ADT1]

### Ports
CLK+ (out), CLK- (out), Clock (in)

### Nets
GND: C28.1 C37.2
NetC28_2: C28.2 T4.1
NetC32_1: C32.1 ; port Clock
NetC32_2: C32.2 T4.3
NetC35_1: C35.1 R31.1 T4.4 ; port CLK+
NetC35_2: C35.2 R31.2 T4.6 ; port CLK-
NetC37_1: C37.1 T4.2 T4.5

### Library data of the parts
C28 C32 C37 = Capacitor_4: CAP CER 0.1UF 16V X7R 0603; Manufacturer: Murata; Manufacturer P/N: GRM188R71C104KA01D; Catalog Number: CAP00036; fiX_Func: Clock signal (6)
C35 = Capacitor_3: CAP CER 33PF 50V NP0 0402; Manufacturer: Murata; Manufacturer P/N: GRM1555C1H330JZ01D; Catalog Number: CAP00038; fiX_Func: Clock signal (6); SDTA_V(Voltage): 3
R31 = Resistor_3: RES SMD 100 OHM 1% 1/16W 0402; Manufacturer P/N: CRCW0402100RFKED; Manufacturer: Vishay; Catalog Number: RES00014; fiX_Func: Clock signal (6); SDTA_P(Power): 0.09; SDTA_Par6(PowerPeak): 4; SDTA_V(Voltage): 3
T4 = ADT1_2: RF TRANSF 75 OHM 0.4-800 MHz; Manufacturer: Mini-Circuits; fiX_Manuf: Texas Instruments; Catalog Number: IND00008; fiX_Func: Clock signal (6)

## Sheet [8]Eeprom.SchDoc: Eeprom
size A4; Organization: BQR; Address1: Reliability Engineering; Address2: Optimized Maintenance; Address3: www.bqr.com; Address4: www.bqr-digital.com; DocumentNumber: DOC9; SheetNumber: 5; SheetTotal: 13
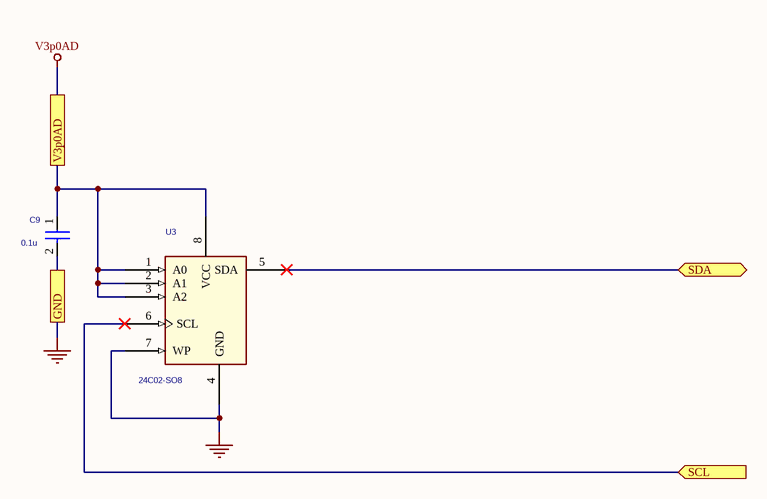
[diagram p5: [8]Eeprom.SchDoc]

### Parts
C9  0.1u  [0603]
U3  24C02-SO8  [soic8_150amps]

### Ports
GND, SCL (in), SDA (bidir), V3p0AD

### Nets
GND: C9.2 U3.4(GND) U3.7(WP) ; port GND
V3p0AD: C9.1 U3.1(A0) U3.2(A1) U3.3(A2) U3.8(VCC) ; port V3p0AD
NetJ1_B3: U3.5(SDA) ; port SDA
NetJ1_C3: U3.6(SCL) ; port SCL

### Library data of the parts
C9 = Capacitor_4: CAP CER 0.1UF 16V X7R 0603; Manufacturer: Murata; Manufacturer P/N: GRM188R71C104KA01D; Catalog Number: CAP00036; SDTA_V(Voltage): 3; fiX_Func: EEPROM (8)
U3 = 24C02-SO8_2: EEPROM 2/4/8/16K 2-WIRE BUS; Manufacturer: Atmel; Manufacturer P/N: AT24C02AN-10SU-2.7; fiX_Manuf: Fairchild; Catalog Number: IC00009; fiX_Func: EEPROM (8)

## Sheet [9]Input Analog Signal.SchDoc: Input Analog Signal
size A4; Organization: BQR; Address1: Reliability Engineering; Address2: Optimized Maintenance; Address3: www.bqr.com; Address4: www.bqr-digital.com; DocumentNumber: 10; SheetNumber: 6; SheetTotal: 13
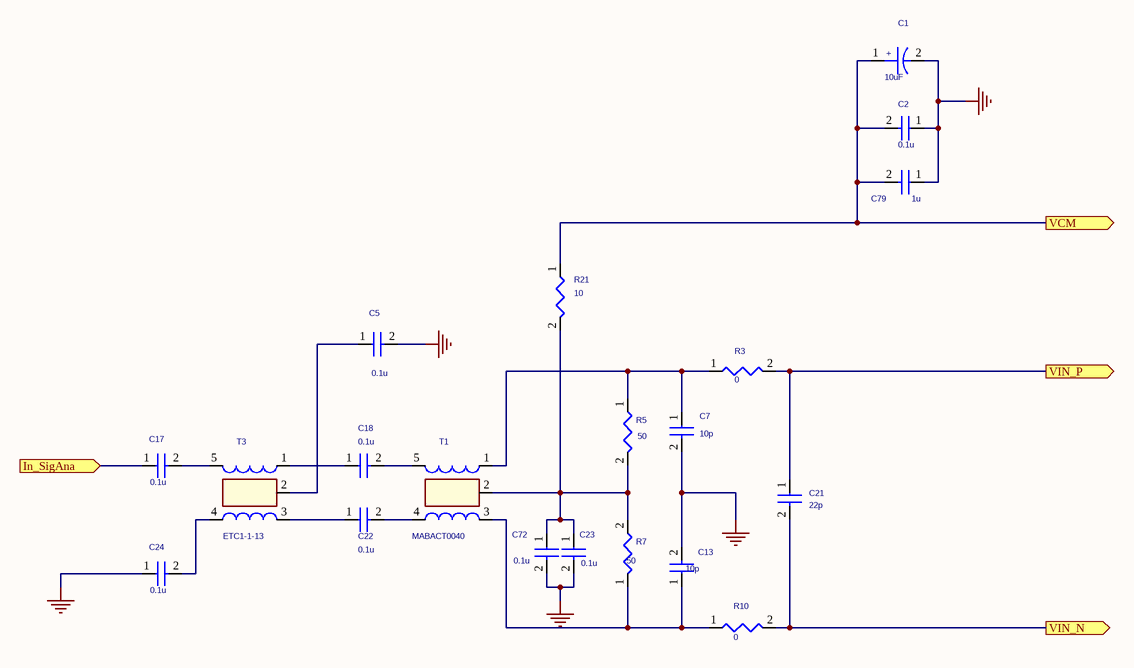
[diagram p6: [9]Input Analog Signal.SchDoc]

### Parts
C1  10uF  [cap_c-case]
C2  0.1u  [0201]
C5  0.1u  [0603]
C7  10p  [0402]
C13  10p  [0402]
C17  0.1u  [0603]
C18  0.1u  [0603]
C21  22p  [0402]
C22  0.1u  [0603]
C23  0.1u  [0603]
C24  0.1u  [0603]
C72  0.1u  [0402]
C79  1u  [0508]
R3  0  [0402]
R5  50  [0402]
R7  50  [0402]
R10  0  [0402]
R21  10  [0603]
T1  MABACT0040  [etc1-1-13]
T3  ETC1-1-13  [etc1-1-13]

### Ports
In_SigAna (in), VCM (out), VIN_N (out), VIN_P (out)

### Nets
GND: C1.2 C2.1 C5.2 C7.2 C13.2 C23.2 C24.1 C72.2 C79.1
NetC1_1: C1.1 C2.2 C79.2 R21.1 ; port VCM
NetC5_1: C5.1 T3.2
NetC7_1: C7.1 R3.1 R5.1 T1.1
NetC13_1: C13.1 R7.1 R10.1 T1.3
NetC17_1: C17.1 ; port In_SigAna
NetC17_2: C17.2 T3.5
NetC18_1: C18.1 T3.1
NetC18_2: C18.2 T1.5
NetC21_1: C21.1 R3.2 ; port VIN_P
NetC21_2: C21.2 R10.2 ; port VIN_N
NetC22_1: C22.1 T3.3
NetC22_2: C22.2 T1.4
NetC23_1: C23.1 C72.1 R5.2 R7.2 R21.2 T1.2
NetC24_2: C24.2 T3.4

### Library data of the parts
C1 = Cap_Polar_1: CAP TANT 10UF 20V 10% 2312; Manufacturer P/N: TAJC106K020R; Manufacturer: AVX; fiX_Manuf: Murata; Catalog Number: CAP00001; fiX_Func: Input circuit (4)
C2 = Capacitor_4: CAP CER 0.1UF 6.3V X5R 0201; Manufacturer P/N: GRM033R60J104KE19D; Manufacturer: Murata; Catalog Number: CAP00002; fiX_Func: Input circuit (4)
C5 C17 C18 C22 C24 = Capacitor_4: CAP CER 0.1UF 16V X7R 0603; Manufacturer: Murata; Manufacturer P/N: GRM188R71C104KA01D; Catalog Number: CAP00036; fiX_Func: Input circuit (4)
C7 = Capacitor_4: CAP CER 10PF 50V NP0 0402; Manufacturer: Murata; Manufacturer P/N: GRM1555C1H100JZ01D; Catalog Number: CAP00029; fiX_Func: Input circuit (4)
C13 = Capacitor_4: CAP CER 10PF 50V NP0 0402; Manufacturer P/N: GRM1555C1H100JZ01D; Manufacturer: Murata; Catalog Number: CAP00029; fiX_Func: Input circuit (4)
C21 = Capacitor_4: CAP CER 22PF 50V NP0 0402; Manufacturer P/N: GRM1555C1H220JZ01D; Manufacturer: Murata; Catalog Number: CAP00037; fiX_Func: Input circuit (4)
C23 = Capacitor_4: CAP CER 0.1UF 16V X7R 0603; Manufacturer: Murata; Manufacturer P/N: GRM188R71C104KA01D; Catalog Number: CAP00036; SDTA_V(Voltage): 5; fiX_Func: Input circuit (4)
C72 = Capacitor_4: CAP CER 0.1UF 10V X5R 0402; Manufacturer P/N: GRM155R61A104KA01D; Manufacturer: Murata; Catalog Number: CAP00026; SDTA_V(Voltage): 5; fiX_Func: Input circuit (4)
C79 = Capacitor_4: CAP CER 1UF 10V X5R 0508; Manufacturer P/N: ECY-29RA105KV; Manufacturer: Panasonic; fiX_Manuf: AVX; Catalog Number: CAP00020; fiX_Func: Input circuit (4)
R3 R10 = Resistor_3: RES SMD 0.0OHM JUMPER 1/16W 0402; Manufacturer: Vishay; Manufacturer P/N: CRCW04020000Z0ED; Catalog Number: RES00015; fiX_Func: Input circuit (4)
R5 R7 = Resistor_3: RES SMD 49.9 OHM 1% 1/16W 0402; Manufacturer P/N: CRCW040249R9FKED; Manufacturer: Vishay; Catalog Number: RES00012; fiX_Func: Input circuit (4)
R21 = Resistor_3: RES SMD 10 OHM 1% 1/10W 0603; Manufacturer P/N: CRCW060310R0FKEA; Manufacturer: Vishay; Catalog Number: RES00013; fiX_Func: Input circuit (4)
T1 = ETC1-1-13: Transformers Audio & Signal 5-1000MHz IL 1.1dB Ctr Tap -40C +85C; Manufacturer: MA-COM; Catalog Number: IND00032; fiX_Func: Input circuit (4)
T3 = ETC1-1-13: TRANSFORMER; Manufacturer: MA-COM; fiX_Manuf: Mini-Circuits; Catalog Number: IND00021; fiX_Func: Input circuit (4)

## Sheet [11]Advanced Power Supply 3VA.SchDoc: Advanced Power Supply 3VA
size A4; Organization: BQR; Address1: Reliability Engineering; Address2: Optimized Maintenance; Address3: www.bqr.com; Address4: www.bqr-digital.com; DocumentNumber: DOC12; SheetNumber: 7; SheetTotal: 13
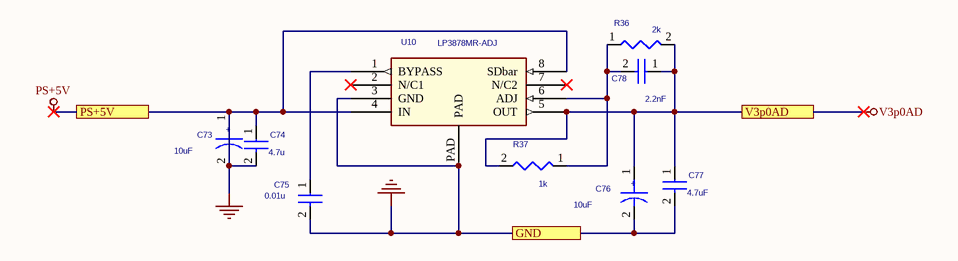
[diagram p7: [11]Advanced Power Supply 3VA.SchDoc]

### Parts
C73  10uF  [cap_c-case]
C74  4.7u  [0603]
C75  0.01u  [0603]
C76  10uF  [cap_c-case]
C77  4.7uF  [0603]
C78  2.2nF  [0603]
R36  2k  [0603]
R37  1k  [0603]
U10  LP3878MR-ADJ  [lp3878-adj_mra08a-psop]

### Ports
GND, PS+5V, V3p0AD

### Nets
GND: C73.1 C73.2 C74.1 C74.2 C75.2 C76.2 C77.2 U10.3(GND) U10.4(IN) U10.8(SDbar) U10.PAD ; port PS+5V, port GND  [also labelled PS+5V]
V3p0AD: C76.1 C77.1 C78.1 R36.2 R37.2 U10.5(OUT) ; port V3p0AD
NetC75_1: C75.1 U10.1(BYPASS)
NetC78_2: C78.2 R36.1 R37.1 U10.6(ADJ)

Not connected (* = marked no-connect by the designer): U10 2(N/C1)* 7(N/C2)*

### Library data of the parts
C73 = Cap_Polar_1: CAP TANT 10UF 20V 10% 2312; Manufacturer P/N: TAJC106K020R; Manufacturer: AVX; fiX_Manuf: Murata; Catalog Number: CAP00001; SDTA_I(Isurge): 0.001; SDTA_V(Voltage): 5; fiX_Func: Advanced Power Supply 3V (2)
C74 = Capacitor_3: CAP CER 4.7UF 6.3V X5R 0603; Manufacturer P/N: ECJ-1VB0J475M; Manufacturer: Panasonic; Catalog Number: CAP00017; SDTA_V(Voltage): 5; fiX_Func: Advanced Power Supply 3V (2)
C75 = Capacitor_3: CAP CER 10000PF 50V X7R 0603; Manufacturer P/N: ECJ-1VB1H103K; Manufacturer: Panasonic; fiX_Manuf: AVX; Catalog Number: CAP00018; fiX_Func: Advanced Power Supply 3V (2); SDTA_V(Voltage): 5
C76 = Cap_Polar_1: CAP TANT 10UF 20V 10% 2312; Manufacturer P/N: TAJC106K020R; Manufacturer: AVX; fiX_Manuf: Murata; Catalog Number: CAP00001; SDTA_V(Voltage): 3; fiX_Func: Advanced Power Supply 3V (2)
C77 = Capacitor_3: CAP CER 4.7UF 6.3V X5R 0603; Manufacturer: Panasonic; Manufacturer P/N: ECJ-1VB0J475M; Catalog Number: CAP00017; SDTA_V(Voltage): 3; fiX_Func: Advanced Power Supply 3V (2)
C78 = Cap_1: CAP CER 2200PF 50V X7R 0603; Manufacturer P/N: ECJ-1VB1H222K; Manufacturer: Panasonic; fiX_Manuf: Murata; Catalog Number: CAP00019; fiX_Func: Advanced Power Supply 3V (2)
R36 = Resistor_3: RES SMD 2K OHM 1% 1/10W 0603; Manufacturer P/N: CRCW06032K00FKEA; Manufacturer: Vishay; Catalog Number: RES00011; fiX_Func: Advanced Power Supply 3V (2)
R37 = Resistor_3: RES SMD 1K OHM 1% 1/10W 0603; Manufacturer P/N: CRCW06031K00FKEA; Manufacturer: Vishay; Catalog Number: RES00010; fiX_Func: Advanced Power Supply 3V (2)
U10 = LP3878MR-ADJ_5: Linear Voltage Regulator IC Positive Adjustable 1 Output 1 V ~ 5.5 V 800mA 8-SO PowerPad; Manufacturer P/N: LP3878MR-ADJ/NOPB; Manufacturer: Texas Instruments; Catalog Number: IC00030; fiX_Func: Advanced Power Supply 3V (2)

## Sheet [12]Input DC Filter.SchDoc: Input DC Filter
size A4; Organization: BQR; Address1: Reliability Engineering; Address2: Optimized Maintenance; Address3: www.bqr.com; Address4: www.bqr-digital.com; DocumentNumber: DOC13; SheetNumber: 8; SheetTotal: 13
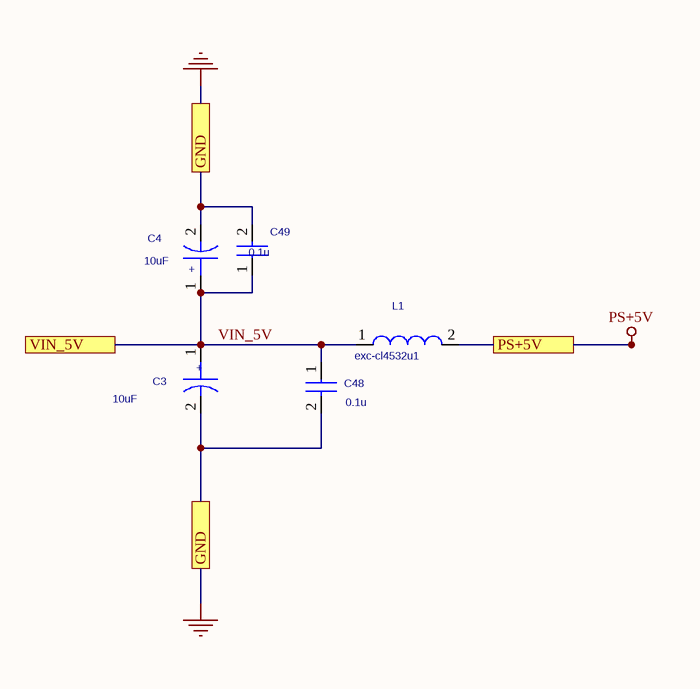
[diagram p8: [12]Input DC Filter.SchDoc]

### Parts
C3  10uF  [cap_c-case]
C4  10uF  [cap_c-case]
C48  0.1u  [0603]
C49  0.1u  [0603]
L1  exc-cl4532u1  [exc-cl4532u1]

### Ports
GND, PS+5V, VIN_5V

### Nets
GND: C3.2 C4.2 C48.2 C49.2 L1.2 ; port PS+5V, port GND  [also labelled PS+5V]
VIN_5V: C3.1 C4.1 C48.1 C49.1 L1.1 ; port VIN_5V

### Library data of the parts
C3 = Cap_Polar_1: CAP TANT 10UF 6.3V 10% 1206; Manufacturer: AVX_1; Manufacturer P/N: TAJA106K006R; fiX_Manuf: Murata; Catalog Number: CAP00039; fiX_Func: DC Filter (12); SDTA_V(Voltage): 5
C4 = Cap_Polar_1: CAP TANT 10UF 20V 10% 2312; Manufacturer P/N: TAJC106K020R; Manufacturer: AVX; fiX_Manuf: Murata; Catalog Number: CAP00001; SDTA_I(Isurge): 0.0001; SDTA_Par5(Vrev): 0.001; SDTA_V(Voltage): 5; fiX_Func: DC Filter (12)
C48 = Capacitor_3: CAP CER 0.1UF 16V X7R 0603; Manufacturer: Murata; Manufacturer P/N: GRM188R71C104KA01D; Catalog Number: CAP00036; fiX_Func: DC Filter (12); SDTA_V(Voltage): 5
C49 = Capacitor_3: CAP CER 0.1UF 16V X7R 0603; Manufacturer: Murata; Manufacturer P/N: GRM188R71C104KA01D; Catalog Number: CAP00036; SDTA_V(Voltage): 5; fiX_Func: DC Filter (12)
L1 = Inductor: FERRITE BEAD 115 OHM 1812 1LN; Manufacturer: Panasonic; fiX_Manuf: JST; Catalog Number: IND00022; fiX_Func: DC Filter (12); SDTA_I(Ioper): 0.07; SDTA_P(Power): 0.15; SDTA_V(Vdiel): 5

## Sheet Decoding.SchDoc: Decoding Code 1&2
size A4; Organization: BQR; Address1: Reliability Engineering; Address2: Optimized Maintenance; Address3: www.bqr.com; Address4: www.bqr-digital.com
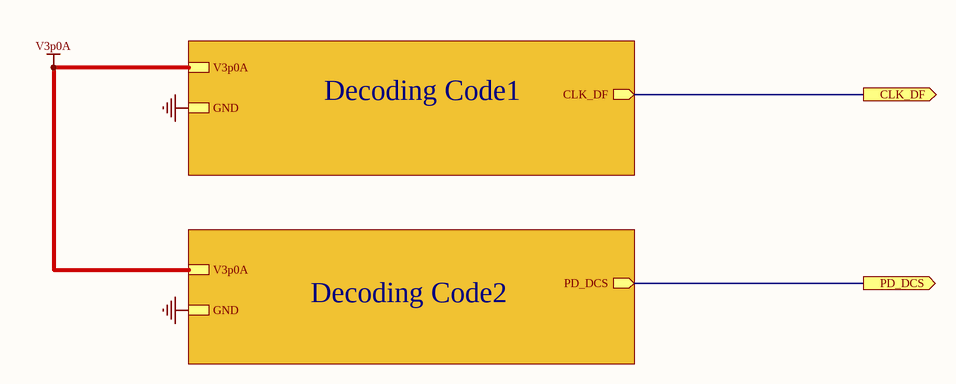
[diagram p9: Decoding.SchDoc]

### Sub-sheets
Decoding Code1 = [1]Decoding Code1.SchDoc: GND, CLK_DF (out), V3p0A
Decoding Code2 = [10]Decoding Code2.SchDoc: PD_DCS (out), V3p0A, GND

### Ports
CLK_DF (out), PD_DCS (out)

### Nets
GND: sheet Decoding Code1/GND, sheet Decoding Code2/GND
V3p0A: sheet Decoding Code1/V3p0A, sheet Decoding Code2/V3p0A
NetJP1_2: port CLK_DF, sheet Decoding Code1/CLK_DF
NetJP2_2: port PD_DCS, sheet Decoding Code2/PD_DCS

## Sheet [1]Decoding Code1.SchDoc: Decoding Code 1
size A4; Organization: BQR; Address1: Reliability Engineering; Address2: Optimized Maintenance; Address3: www.bqr.com; Address4: www.bqr-digital.com; DocumentNumber: DOC2; SheetNumber: 10; SheetTotal: 13
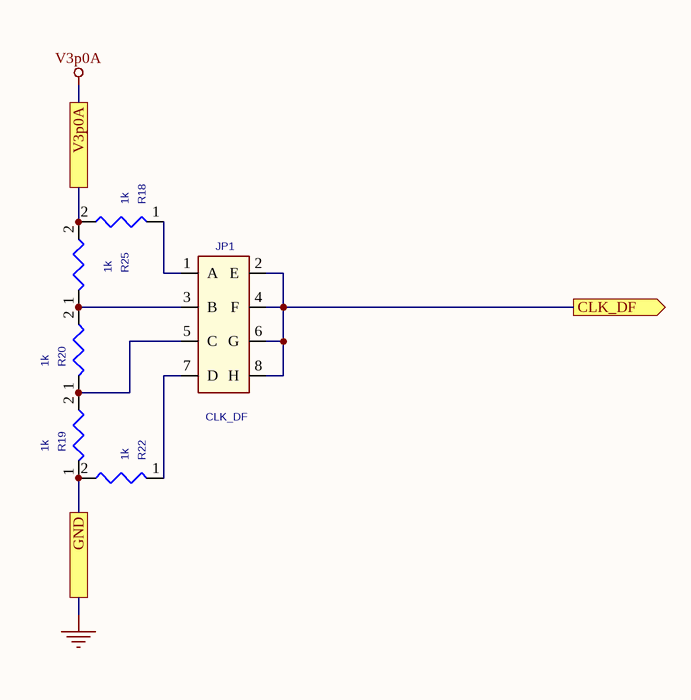
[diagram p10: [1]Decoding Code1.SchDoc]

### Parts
JP1  CLK_DF  [hdr-2x4-100]
R18  1k  [0603]
R19  1k  [0603]
R20  1k  [0603]
R22  1k  [0603]
R25  1k  [0603]

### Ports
CLK_DF (out), GND, V3p0A

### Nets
GND: R19.1 R22.2 ; port GND
V3p0A: R18.2 R25.2 ; port V3p0A
NetJP1_1: JP1.1(A) R18.1
NetJP1_2: JP1.2(E) JP1.4(F) JP1.6(G) JP1.8(H) ; port CLK_DF
NetJP1_3: JP1.3(B) R20.2 R25.1
NetJP1_5: JP1.5(C) R19.2 R20.1
NetJP1_7: JP1.7(D) R22.1

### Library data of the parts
JP1 = HDR-2x4_0: 8 Positions Header, Unshrouded Connector 0.100" (2.54mm) Through Hole Gold; Manufacturer P/N: TSW-104-07-F-D; Manufacturer: Samtec; Catalog Number: CON00035; fiX_Func: ADC (10)
R18-R20 R22 R25 = Resistor_3: RES SMD 1K OHM 1% 1/10W 0603; Manufacturer P/N: CRCW06031K00FKEA; Manufacturer: Vishay; Catalog Number: RES00010; fiX_Func: ADC (10)

## Sheet [10]Decoding Code2.SchDoc: Decoding Code2
size A4; Organization: BQR; Address1: Reliability Engineering; Address2: Optimized Maintenance; Address3: www.bqr.com; Address4: www.bqr-digital.com; DocumentNumber: DOC11; SheetNumber: 11; SheetTotal: 13
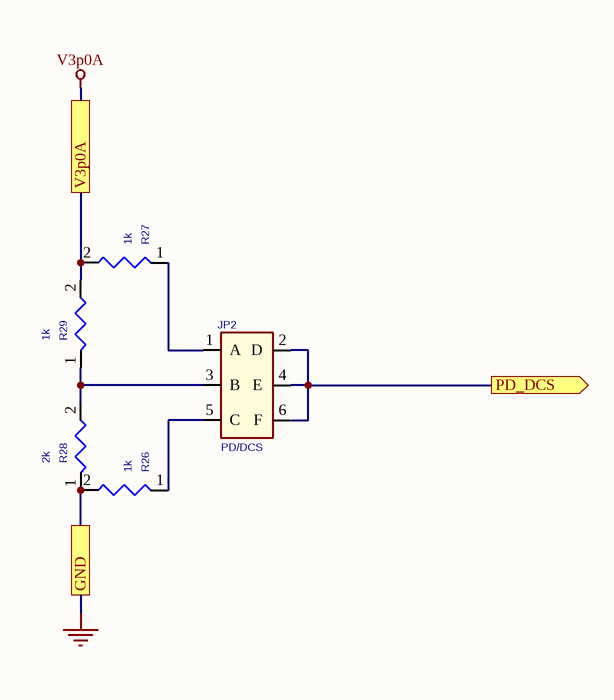
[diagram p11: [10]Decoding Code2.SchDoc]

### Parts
JP2  PD/DCS  [hdr-2x3-100]
R26  1k  [0603]
R27  1k  [0603]
R28  2k  [0603]
R29  1k  [0603]

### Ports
GND, PD_DCS (out), V3p0A

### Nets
GND: R26.2 R28.1 ; port GND
V3p0A: R27.2 R29.2 ; port V3p0A
NetJP2_1: JP2.1(A) R27.1
NetJP2_2: JP2.2(D) JP2.4(E) JP2.6(F) ; port PD_DCS
NetJP2_3: JP2.3(B) R28.2 R29.1
NetJP2_5: JP2.5(C) R26.1

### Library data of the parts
JP2 = HDR-2x3: 6 Positions Header, Unshrouded Connector 0.100" (2.54mm) Through Hole Gold; Manufacturer P/N: TSW-103-07-F-D; Manufacturer: Samtec; fiX_Manuf: Panasonic; Catalog Number: CON00034; fiX_Func: ADC (10)
R26 R27 R29 = Resistor_3: as R18 on sheet [1]Decoding Code1
R28 = Resistor_3: RES SMD 2K OHM 1% 1/10W 0603; Manufacturer P/N: CRCW06032K00FKEA; Manufacturer: Vishay; Catalog Number: RES00011; fiX_Func: ADC (10)

## Sheet Advanced Power Supply.SchDoc: Advanced Power Supply
size A4; Organization: BQR; Address1: Reliability Engineering; Address2: Optimized Maintenance; Address3: www.bqr.com; Address4: www.bqr-digital.com; SheetNumber: 12; SheetTotal: 13
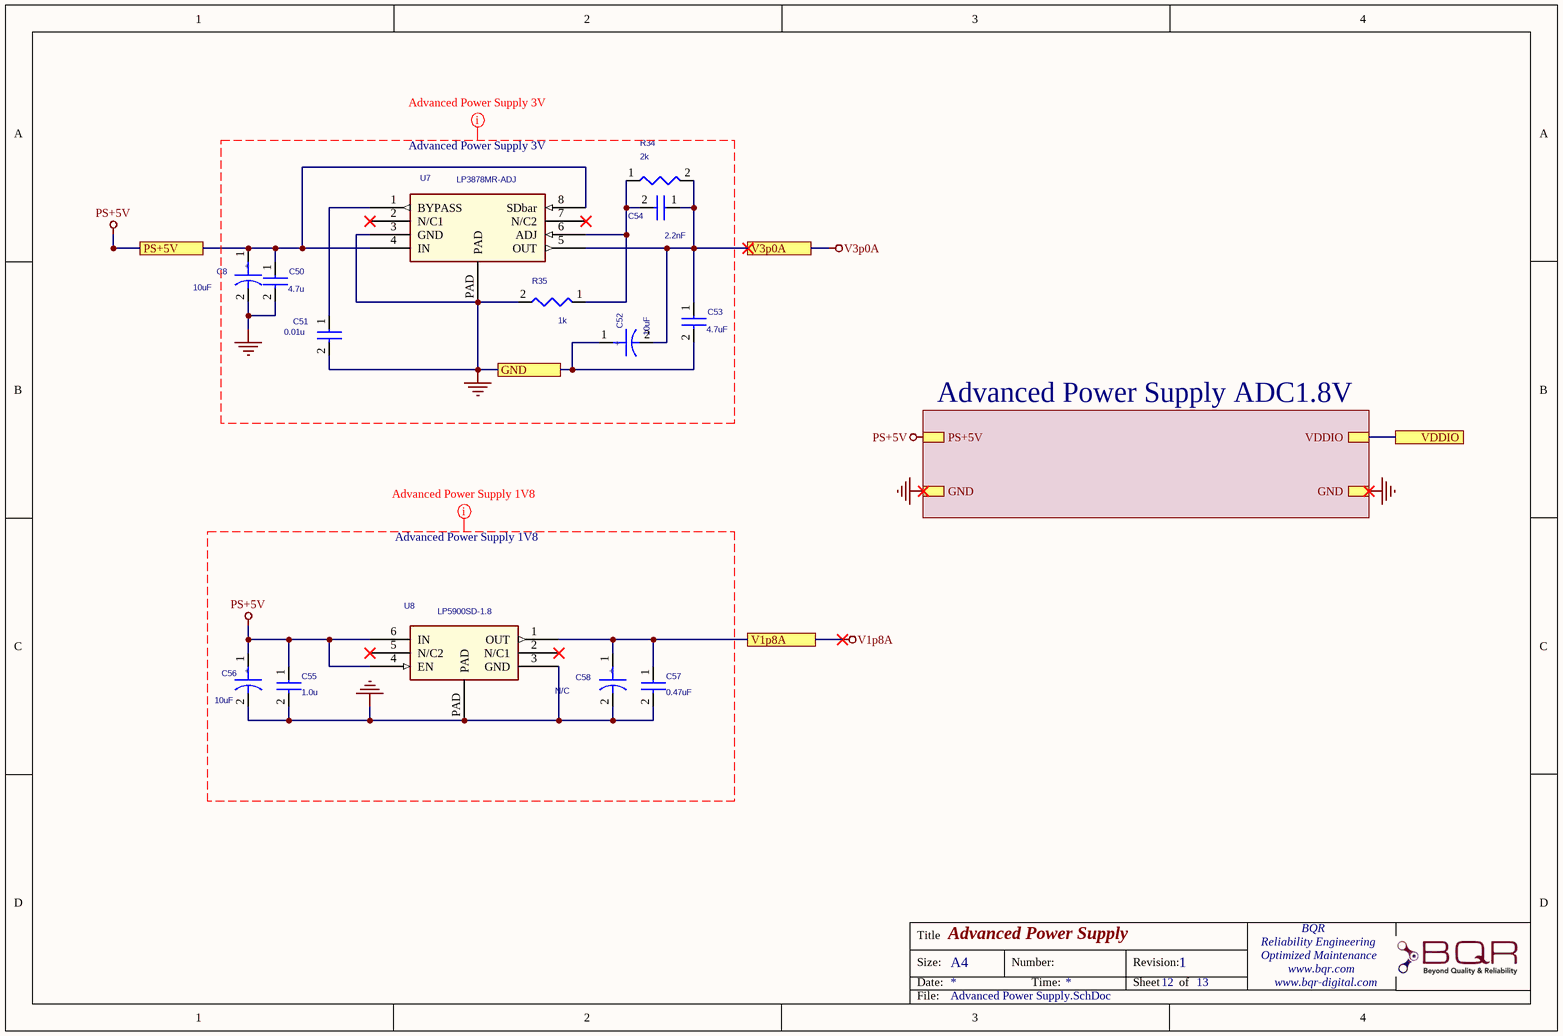
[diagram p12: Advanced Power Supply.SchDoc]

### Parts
C8  10uF  [cap_c-case]
C50  4.7u  [0603]
C51  0.01u  [0603]
C52  10uF  [cap_c-case]
C53  4.7uF  [0603]
C54  2.2nF  [0603]
C55  1.0u  [0603]
C56  10uF  [cap_c-case]
C57  0.47uF  [0603]
C58  N/C  [cap_c-case]
R34  2k  [0603]
R35  1k  [0603]
U7  LP3878MR-ADJ  [lp3878-adj_mra08a-psop]
U8  LP5900SD-1.8  [lp5900_sdb06a-llp6]

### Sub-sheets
Advanced Power Supply ADC1.8V = [7]Advanced Power Supply for ADC1.8V.SchDoc: VDDIO, PS+5V, GND, GND

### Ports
GND, PS+5V, V1p8A, V3p0A, VDDIO

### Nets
GND: C8.1 C8.2 C50.1 C50.2 C51.2 C52.1 C53.2 C55.1 C55.2 C56.1 C56.2 C57.2 C58.2 R35.2 U7.3(GND) U7.4(IN) U7.8(SDbar) U7.PAD U8.3(GND) U8.4(EN) U8.6(IN) U8.PAD ; port PS+5V, port GND, sheet Advanced Power Supply ADC1.8V/PS+5V, sheet Advanced Power Supply ADC1.8V/GND, sheet Advanced Power Supply ADC1.8V/GND  [also labelled PS+5V]
V1p8A: C57.1 C58.1 U8.1(OUT) ; port V1p8A
V3p0A: C52.2 C53.1 C54.1 R34.2 U7.5(OUT) ; port V3p0A
VDDIO: port VDDIO, sheet Advanced Power Supply ADC1.8V/VDDIO
NetC51_1: C51.1 U7.1(BYPASS)
NetC54_2: C54.2 R34.1 R35.1 U7.6(ADJ)

Not connected (* = marked no-connect by the designer): U7 2(N/C1)* 7(N/C2)*; U8 2(N/C1)* 5(N/C2)*

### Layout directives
CompClassName: Advanced Power Supply 3V: GND
CompClassName: Advanced Power Supply 1V8: GND, PS+5V

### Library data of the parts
C8 = Cap_Polar_1: CAP TANT 10UF 20V 10% 2312; Manufacturer P/N: TAJC106K020R; Manufacturer: AVX; fiX_Manuf: Murata; Catalog Number: CAP00001; SDTA_I(Isurge): 0.001; SDTA_V(Voltage): 5; fiX_Func: Advanced Power Supply 3V A (11)
C50 = Capacitor_3: CAP CER 4.7UF 6.3V X5R 0603; Manufacturer: Panasonic; Manufacturer P/N: ECJ-1VB0J475M; Catalog Number: CAP00017; SDTA_V(Voltage): 5; fiX_Func: Advanced Power Supply 3V A (11)
C51 = Capacitor_3: CAP CER 10000PF 50V X7R 0603; Manufacturer P/N: ECJ-1VB1H103K; Manufacturer: Panasonic; fiX_Manuf: AVX; Catalog Number: CAP00018; fiX_Func: Advanced Power Supply 3V A (11); SDTA_V(Voltage): 5
C52 = Cap_Polar_1: CAP TANT 10UF 20V 10% 2312; Manufacturer P/N: TAJC106K020R; Manufacturer: AVX; fiX_Manuf: Murata; Catalog Number: CAP00001; SDTA_V(Voltage): 3; fiX_Func: Advanced Power Supply 3V A (11)
C53 = Capacitor_3: CAP CER 4.7UF 6.3V X5R 0603; Manufacturer P/N: ECJ-1VB0J475M; Manufacturer: Panasonic; Catalog Number: CAP00017; SDTA_V(Voltage): 3; fiX_Func: Advanced Power Supply 3V A (11)
C54 = Cap_1: CAP CER 2200PF 50V X7R 0603; Manufacturer P/N: ECJ-1VB1H222K; Manufacturer: Panasonic; fiX_Manuf: Murata; Catalog Number: CAP00019; fiX_Func: Advanced Power Supply 3V A (11); SDTA_V(Voltage): 6
C55 = Capacitor_3: CAP CER 1UF 16V X7R 0603; Manufacturer: Murata; Manufacturer P/N: GRM188R71C105KA12D; fiX_Manuf: AVX; Catalog Number: CAP00028; SDTA_V(Voltage): 5; fiX_Func: Advanced Power Supply 1.8V (3)
C56 = Cap_Polar_1: CAP TANT 10UF 20V 10% 2312; Manufacturer P/N: TAJC106K020R; Manufacturer: AVX; fiX_Manuf: Murata; Catalog Number: CAP00001; SDTA_I(Isurge): 0.001; SDTA_V(Voltage): 5; fiX_Func: Advanced Power Supply 1.8V (3)
C57 = Capacitor_3: CAP CER 0.47UF 6.3V X5R 0603; Manufacturer P/N: ECJ-1VB0J474K; Manufacturer: Panasonic; fiX_Manuf: AVX; Catalog Number: CAP00016; SDTA_V(Voltage): 1.8; fiX_Func: Advanced Power Supply 1.8V (3)
C58 = Cap_Polar_1: CAP TANT 10UF 20V 10% 2312; Manufacturer P/N: TAJC106K020R; Manufacturer: AVX; fiX_Manuf: Murata; Catalog Number: CAP00001; SDTA_V(Voltage): 1.8; fiX_Func: Advanced Power Supply 1.8V (3)
R34 = Resistor_3: RES SMD 2K OHM 1% 1/10W 0603; Manufacturer P/N: CRCW06032K00FKEA; Manufacturer: Vishay; Catalog Number: RES00011; fiX_Func: Advanced Power Supply 3V A (11); SDTA_P(Power): 0.018; SDTA_V(Voltage): 6; Filename: AdvPwr3V
R35 = Resistor_3: RES SMD 1K OHM 1% 1/10W 0603; Manufacturer P/N: CRCW06031K00FKEA; Manufacturer: Vishay; Catalog Number: RES00010; fiX_Func: Advanced Power Supply 3V A (11); Filename: AdvPwr3V
U7 = LP3878MR-ADJ_4: Linear Voltage Regulator IC Positive Adjustable 1 Output 1 V ~ 5.5 V 800mA 8-SO PowerPad; Manufacturer: Texas Instruments; Manufacturer P/N: LP3878MR-ADJ/NOPB; Catalog Number: IC00030; fiX_Func: Advanced Power Supply 3V A (11); SDTA_I(Iout): 2; SDTA_V(Vsupply): 20; Filename: AdvPwr3V
U8 = LP5900SD-1_0.8: IC REG LDO 1.8V 0.15A 6WSON; Manufacturer: Texas Instruments; Manufacturer P/N: LP5900SD-1.8/NOPB; Catalog Number: IC00031; fiX_Func: Advanced Power Supply 1.8V (3); Filename: AdvPwr1V8

## Sheet [7]Advanced Power Supply for ADC1.8V.SchDoc: Advanced Power Supply for ADC1.8V
size A4; Organization: BQR; Address1: Reliability Engineering; Address2: Optimized Maintenance; Address3: www.bqr.com; Address4: www.bqr-digital.com; DocumentNumber: DOC8; SheetNumber: 13; SheetTotal: 13
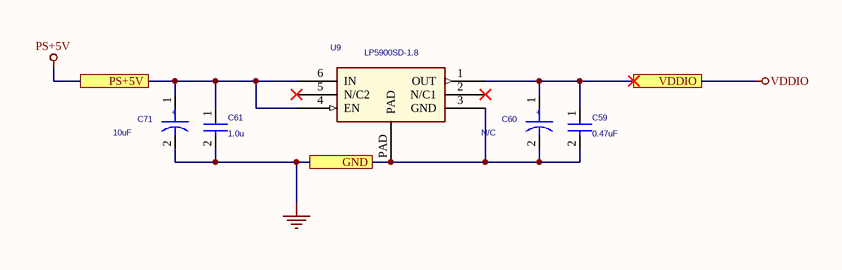
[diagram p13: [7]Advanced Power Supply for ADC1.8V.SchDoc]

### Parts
C59  0.47uF  [0603]
C60  N/C  [cap_c-case]
C61  1.0u  [0603]
C71  10uF  [cap_c-case]
U9  LP5900SD-1.8  [lp5900_sdb06a-llp6]

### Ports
GND, PS+5V, VDDIO

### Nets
GND: C59.2 C60.2 C61.1 C61.2 C71.1 C71.2 U9.3(GND) U9.4(EN) U9.6(IN) U9.PAD ; port PS+5V, port GND  [also labelled PS+5V]
VDDIO: C59.1 C60.1 U9.1(OUT) ; port VDDIO

Not connected (* = marked no-connect by the designer): U9 2(N/C1)* 5(N/C2)*

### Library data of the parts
C59 = Capacitor_3: CAP CER 0.47UF 6.3V X5R 0603; Manufacturer P/N: ECJ-1VB0J474K; Manufacturer: Panasonic; fiX_Manuf: AVX; Catalog Number: CAP00016; SDTA_V(Voltage): 25; fiX_Func: Advanced Power Supply for ADC 1.8V (7)
C60 = Cap_Polar_1: CAP TANT 10UF 20V 10% 2312; Manufacturer P/N: TAJC106K020R; Manufacturer: AVX; fiX_Manuf: Murata; Catalog Number: CAP00001; SDTA_I(Isurge): 0.01; SDTA_Par5(Vrev): 0.001; SDTA_V(Voltage): 25; fiX_Func: Advanced Power Supply for ADC 1.8V (7)
C61 = Capacitor_3: CAP CER 1UF 16V X7R 0603; Manufacturer P/N: GRM188R71C105KA12D; Manufacturer: Murata; fiX_Manuf: AVX; Catalog Number: CAP00028; SDTA_V(Voltage): 5; fiX_Func: Advanced Power Supply for ADC 1.8V (7)
C71 = Cap_Polar_1: CAP TANT 10UF 20V 10% 2312; Manufacturer P/N: TAJC106K020R; Manufacturer: AVX; fiX_Manuf: Murata; Catalog Number: CAP00001; SDTA_I(Isurge): 0.001; SDTA_V(Voltage): 5; fiX_Func: Advanced Power Supply for ADC 1.8V (7)
U9 = LP5900SD-1_0.8: IC REG LDO 1.8V 0.15A 6WSON; Manufacturer: Texas Instruments; Manufacturer P/N: LP5900SD-1.8/NOPB; Catalog Number: IC00031; fiX_Func: Advanced Power Supply for ADC 1.8V (7)

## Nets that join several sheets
GND: TOP Level (51 pins), [4]ADC16V130 (27 pins), [5]Digital Signal Ouput Buffer & Driver (33 pins), [6]Clock Signal (C28.1 C37.2), [8]Eeprom (C9.2 U3.4 U3.7), [9]Input Analog Signal (9 pins), [11]Advanced Power Supply 3VA (11 pins), [12]Input DC Filter (5 pins), [1]Decoding Code1 (R19.1 R22.2), [10]Decoding Code2 (R26.2 R28.1), Advanced Power Supply (22 pins), [7]Advanced Power Supply for ADC1.8V (10 pins)
V1p8A: [4]ADC16V130 (9 pins), Advanced Power Supply (C57.1 C58.1 U8.1)
V3p0A: [4]ADC16V130 (9 pins), [1]Decoding Code1 (R18.2 R25.2), [10]Decoding Code2 (R27.2 R29.2), Advanced Power Supply (5 pins)
V3p0AD: [5]Digital Signal Ouput Buffer & Driver (27 pins), [8]Eeprom (5 pins), [11]Advanced Power Supply 3VA (6 pins)
VDDIO: [4]ADC16V130 (6 pins), [7]Advanced Power Supply for ADC1.8V (C59.1 C60.1 U9.1)
D0_N: [4]ADC16V130 (U2.15), [5]Digital Signal Ouput Buffer & Driver (R33.1 U6.1)
D0_P: [4]ADC16V130 (U2.16), [5]Digital Signal Ouput Buffer & Driver (R33.2 U6.8)
D1_N: [4]ADC16V130 (U2.17), [5]Digital Signal Ouput Buffer & Driver (RN4.8 U5.4)
D1_P: [4]ADC16V130 (U2.18), [5]Digital Signal Ouput Buffer & Driver (RN4.7 U5.5)
D2_N: [4]ADC16V130 (U2.19), [5]Digital Signal Ouput Buffer & Driver (RN4.6 U5.6)
D2_P: [4]ADC16V130 (U2.20), [5]Digital Signal Ouput Buffer & Driver (RN4.5 U5.7)
D3_N: [4]ADC16V130 (U2.21), [5]Digital Signal Ouput Buffer & Driver (RN4.4 U5.8)
D3_P: [4]ADC16V130 (U2.22), [5]Digital Signal Ouput Buffer & Driver (RN4.3 U5.9)
D4_N: [4]ADC16V130 (U2.25), [5]Digital Signal Ouput Buffer & Driver (RN4.2 U5.10)
D4_P: [4]ADC16V130 (U2.26), [5]Digital Signal Ouput Buffer & Driver (RN4.1 U5.11)
D5_N: [4]ADC16V130 (U2.27), [5]Digital Signal Ouput Buffer & Driver (RN3.8 U5.14 U5.18)
D5_P: [4]ADC16V130 (U2.28), [5]Digital Signal Ouput Buffer & Driver (RN3.7 U5.15)
D6_N: [4]ADC16V130 (U2.29), [5]Digital Signal Ouput Buffer & Driver (RN3.6 U5.16)
D6_P: [4]ADC16V130 (U2.30), [5]Digital Signal Ouput Buffer & Driver (RN3.5 U5.17)
D7_N: [4]ADC16V130 (U2.31), [5]Digital Signal Ouput Buffer & Driver (RN3.4 U5.19)
D7_P: [4]ADC16V130 (U2.32), [5]Digital Signal Ouput Buffer & Driver (RN3.3)
D8_N: [4]ADC16V130 (U2.35), [5]Digital Signal Ouput Buffer & Driver (RN2.8 U4.4)
D8_P: [4]ADC16V130 (U2.36), [5]Digital Signal Ouput Buffer & Driver (RN2.7 U4.5)
D9_N: [4]ADC16V130 (U2.37), [5]Digital Signal Ouput Buffer & Driver (RN2.6 U4.6)
D9_P: [4]ADC16V130 (U2.38), [5]Digital Signal Ouput Buffer & Driver (RN2.5 U4.7)
D10_N: [4]ADC16V130 (U2.39), [5]Digital Signal Ouput Buffer & Driver (RN2.4 U4.8)
D10_P: [4]ADC16V130 (U2.40), [5]Digital Signal Ouput Buffer & Driver (RN2.3 U4.9)
D11_N: [4]ADC16V130 (U2.41), [5]Digital Signal Ouput Buffer & Driver (RN2.2 U4.10)
D11_P: [4]ADC16V130 (U2.42), [5]Digital Signal Ouput Buffer & Driver (RN2.1 U4.11)
D12_N: [4]ADC16V130 (U2.45), [5]Digital Signal Ouput Buffer & Driver (RN1.8 U4.14)
D12_P: [4]ADC16V130 (U2.46), [5]Digital Signal Ouput Buffer & Driver (RN1.7 U4.15)
D13_N: [4]ADC16V130 (U2.47), [5]Digital Signal Ouput Buffer & Driver (RN1.6 U4.16)
D13_P: [4]ADC16V130 (U2.48), [5]Digital Signal Ouput Buffer & Driver (RN1.5 U4.17)
D14_N: [4]ADC16V130 (U2.49), [5]Digital Signal Ouput Buffer & Driver (RN1.3 U4.19)
D14_P: [4]ADC16V130 (U2.50), [5]Digital Signal Ouput Buffer & Driver (RN1.4 U4.18)
D15_N: [4]ADC16V130 (U2.51), [5]Digital Signal Ouput Buffer & Driver (RN1.2 U4.20)
D15_P: [4]ADC16V130 (U2.52), [5]Digital Signal Ouput Buffer & Driver (RN1.1 U4.21)
DCLKO_N: [4]ADC16V130 (U2.33), [5]Digital Signal Ouput Buffer & Driver (RN3.2 U5.20)
DCLKO_P: [4]ADC16V130 (U2.34), [5]Digital Signal Ouput Buffer & Driver (RN3.1 U5.21)
DOUT1+: TOP Level (J1.A12), [5]Digital Signal Ouput Buffer & Driver (U4.44)
DOUT1-: TOP Level (J1.B12), [5]Digital Signal Ouput Buffer & Driver (U4.45)
DOUT2+: TOP Level (J1.B11), [5]Digital Signal Ouput Buffer & Driver (U4.43)
DOUT2-: TOP Level (J1.A11), [5]Digital Signal Ouput Buffer & Driver (U4.42)
DOUT3+: TOP Level (J1.A10), [5]Digital Signal Ouput Buffer & Driver (U4.40)
DOUT3-: TOP Level (J1.B10), [5]Digital Signal Ouput Buffer & Driver (U4.41)
DOUT4+: TOP Level (J1.B9), [5]Digital Signal Ouput Buffer & Driver (U4.39)
DOUT4-: TOP Level (J1.A9), [5]Digital Signal Ouput Buffer & Driver (U4.38)
DOUT5+: TOP Level (J1.A8), [5]Digital Signal Ouput Buffer & Driver (U4.34)
DOUT5-: TOP Level (J1.B8), [5]Digital Signal Ouput Buffer & Driver (U4.35)
DOUT6+: TOP Level (J1.B7), [5]Digital Signal Ouput Buffer & Driver (U4.33)
DOUT6-: TOP Level (J1.A7), [5]Digital Signal Ouput Buffer & Driver (U4.32)
DOUT7+: TOP Level (J1.A6), [5]Digital Signal Ouput Buffer & Driver (U4.30)
DOUT7-: TOP Level (J1.B6), [5]Digital Signal Ouput Buffer & Driver (U4.31)
DOUT8+: TOP Level (J1.B5), [5]Digital Signal Ouput Buffer & Driver (U4.29)
DOUT8-: TOP Level (J1.A5), [5]Digital Signal Ouput Buffer & Driver (U4.28)
DOUT+: TOP Level (J1.A21), [5]Digital Signal Ouput Buffer & Driver (U6.6)
DOUT-: TOP Level (J1.B21), [5]Digital Signal Ouput Buffer & Driver (U6.5)
NetC1_1: [4]ADC16V130 (U2.58), [9]Input Analog Signal (C1.1 C2.2 C79.2 R21.1)
NetC17_1: TOP Level (J2.1), [9]Input Analog Signal (C17.1)
NetC21_1: [4]ADC16V130 (U2.61), [9]Input Analog Signal (C21.1 R3.2)
NetC21_2: [4]ADC16V130 (U2.62), [9]Input Analog Signal (C21.2 R10.2)
NetC32_1: TOP Level (J3.1), [6]Clock Signal (C32.1)
NetC35_1: [4]ADC16V130 (U2.10), [6]Clock Signal (C35.1 R31.1 T4.4)
NetC35_2: [4]ADC16V130 (U2.11 U2.12), [6]Clock Signal (C35.2 R31.2 T4.6)
NetJ1_B3: TOP Level (J1.B3), [8]Eeprom (U3.5)
NetJ1_C3: TOP Level (J1.C3), [8]Eeprom (U3.6)
NetJP1_2: [4]ADC16V130 (U2.1), [1]Decoding Code1 (JP1.2 JP1.4 JP1.6 JP1.8)
NetJP2_2: [4]ADC16V130 (U2.14), [10]Decoding Code2 (JP2.2 JP2.4 JP2.6)
OUT1+: TOP Level (J1.A20), [5]Digital Signal Ouput Buffer & Driver (U5.44)
OUT1-: TOP Level (J1.B20), [5]Digital Signal Ouput Buffer & Driver (U5.45)
OUT2+: TOP Level (J1.B19), [5]Digital Signal Ouput Buffer & Driver (U5.43)
OUT2-: TOP Level (J1.A19), [5]Digital Signal Ouput Buffer & Driver (U5.42)
OUT3+: TOP Level (J1.A18), [5]Digital Signal Ouput Buffer & Driver (U5.40)
OUT3-: TOP Level (J1.B18), [5]Digital Signal Ouput Buffer & Driver (U5.41)
OUT4+: TOP Level (J1.B17), [5]Digital Signal Ouput Buffer & Driver (U5.39)
OUT4-: TOP Level (J1.A17), [5]Digital Signal Ouput Buffer & Driver (U5.38)
OUT5+: TOP Level (J1.A16), [5]Digital Signal Ouput Buffer & Driver (U5.34)
OUT5-: TOP Level (J1.B16), [5]Digital Signal Ouput Buffer & Driver (U5.35)
OUT6+: TOP Level (J1.B15), [5]Digital Signal Ouput Buffer & Driver (U5.33)
OUT6-: TOP Level (J1.A15), [5]Digital Signal Ouput Buffer & Driver (U5.32)
OUT7+: TOP Level (J1.A14), [5]Digital Signal Ouput Buffer & Driver (U5.30)
OUT7-: TOP Level (J1.B14), [5]Digital Signal Ouput Buffer & Driver (U5.31)
OUT8+: TOP Level (J1.B13), [5]Digital Signal Ouput Buffer & Driver (U5.29)
OUT8-: TOP Level (J1.A13), [5]Digital Signal Ouput Buffer & Driver (U5.28)
VIN_5V: TOP Level (P1.1), [12]Input DC Filter (5 pins)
